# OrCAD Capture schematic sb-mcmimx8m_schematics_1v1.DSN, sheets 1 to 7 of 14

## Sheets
1 13. CAN interfaces: size A4; title: SBC-MCM-iMX8M    13. CAN interfaces; rev: 1.0; note: 8000136001; note: 17 HaYetsira Street; note: Yokneam Illit, Israel 2069208
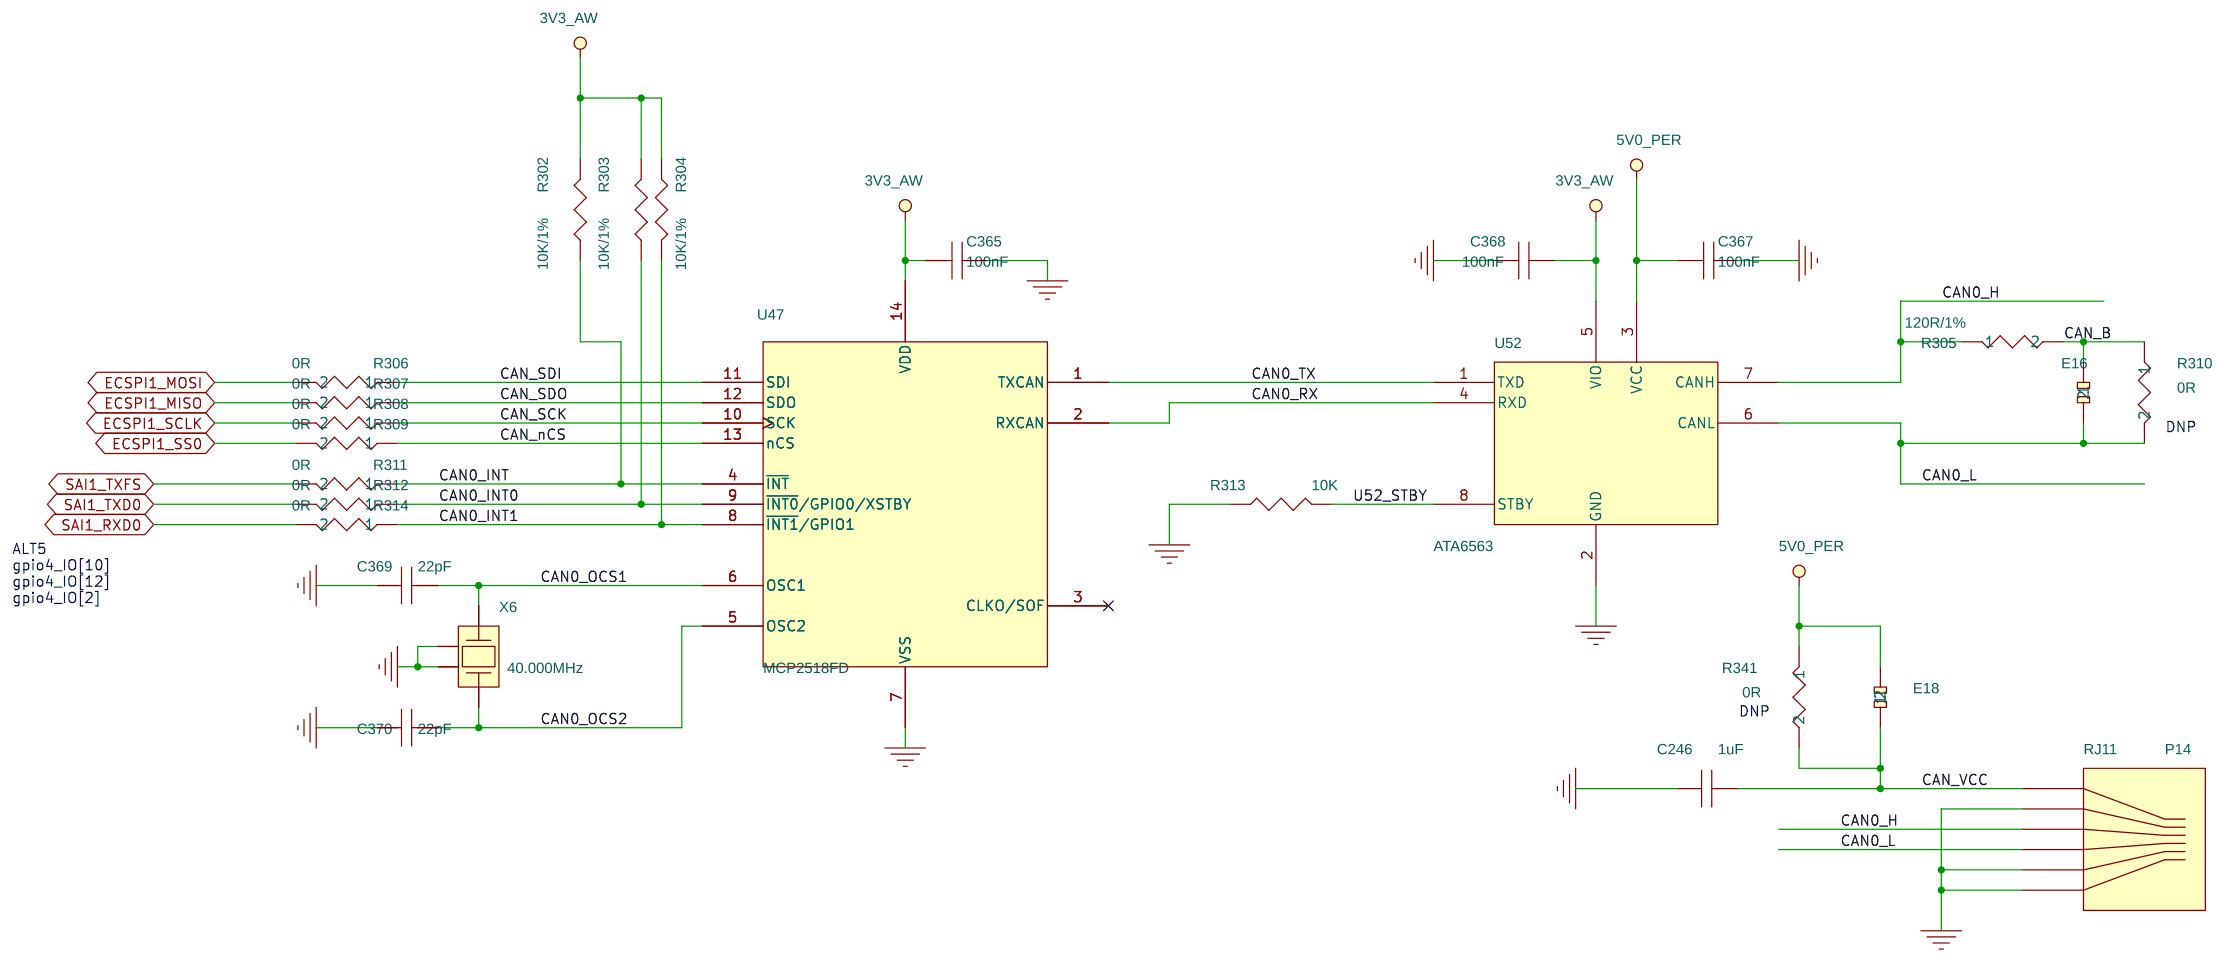
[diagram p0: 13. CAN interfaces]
2 01. Block Diagram: size C; title: SBC-MCM-iMX8M    01. INDEX; rev: 2.0
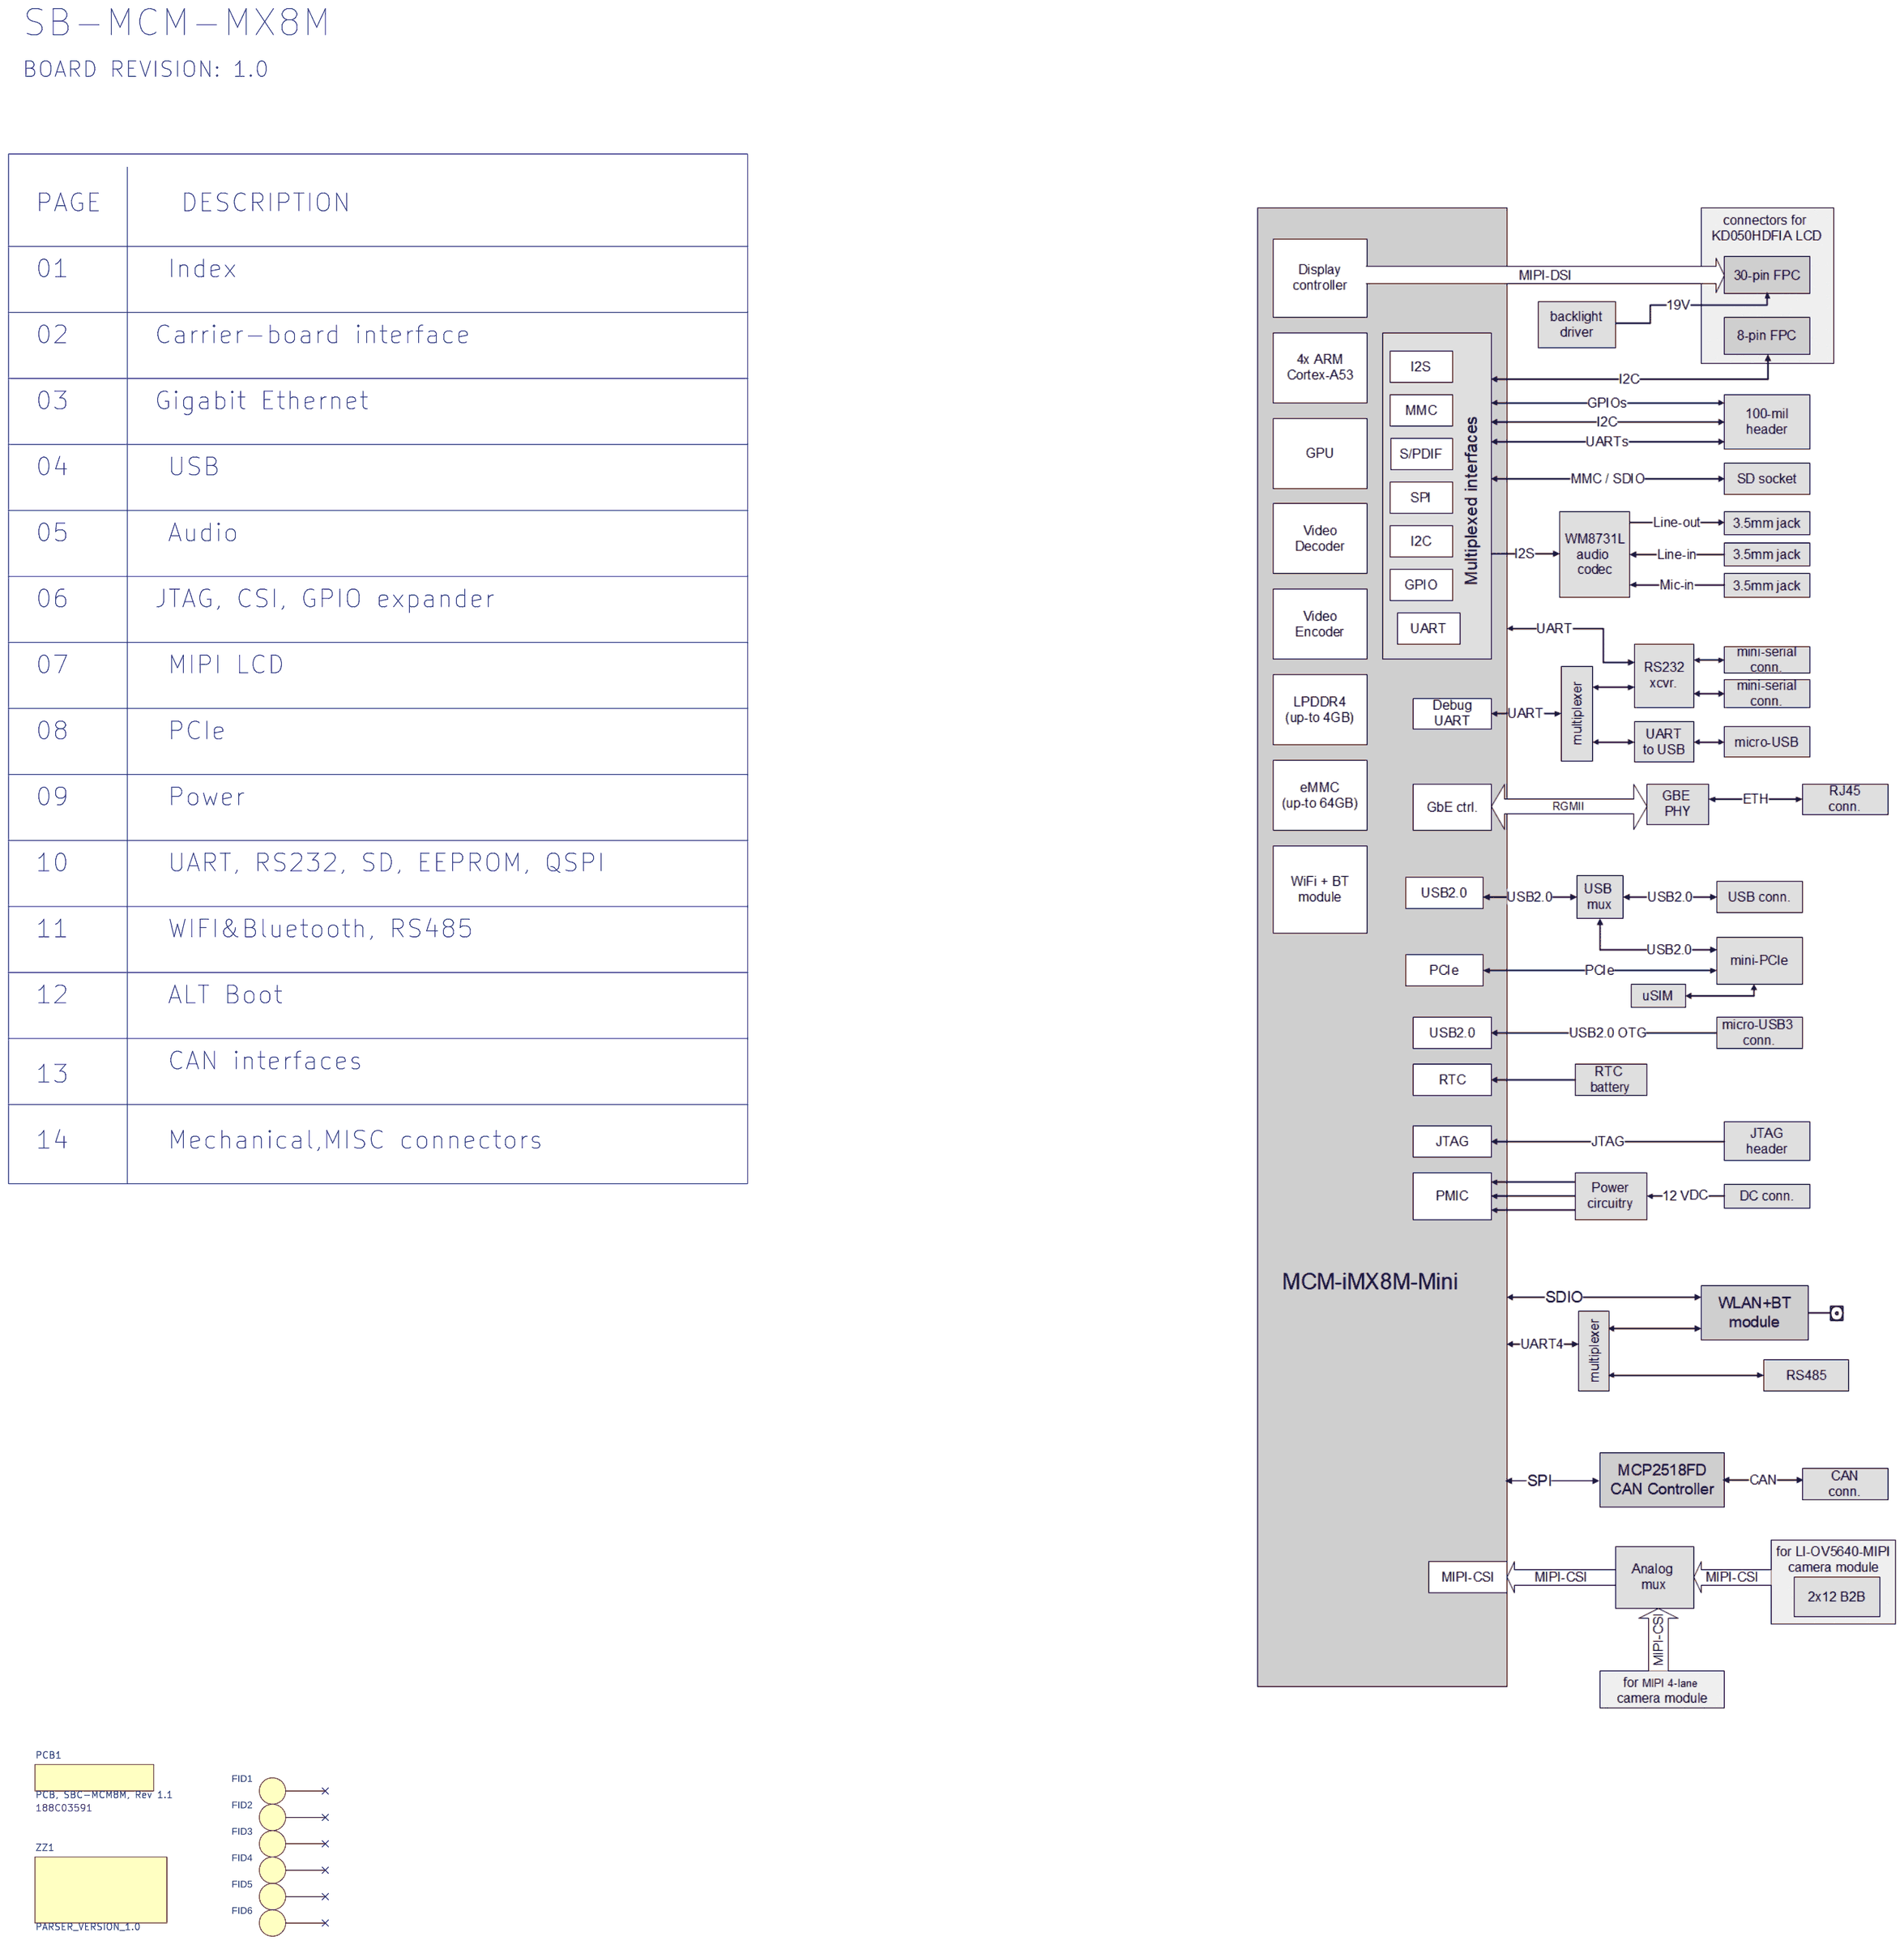
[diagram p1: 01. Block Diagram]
3 02. Carrier Board interface: size A3; title: SBC-MCM-iMX8M    02.140 QFN package
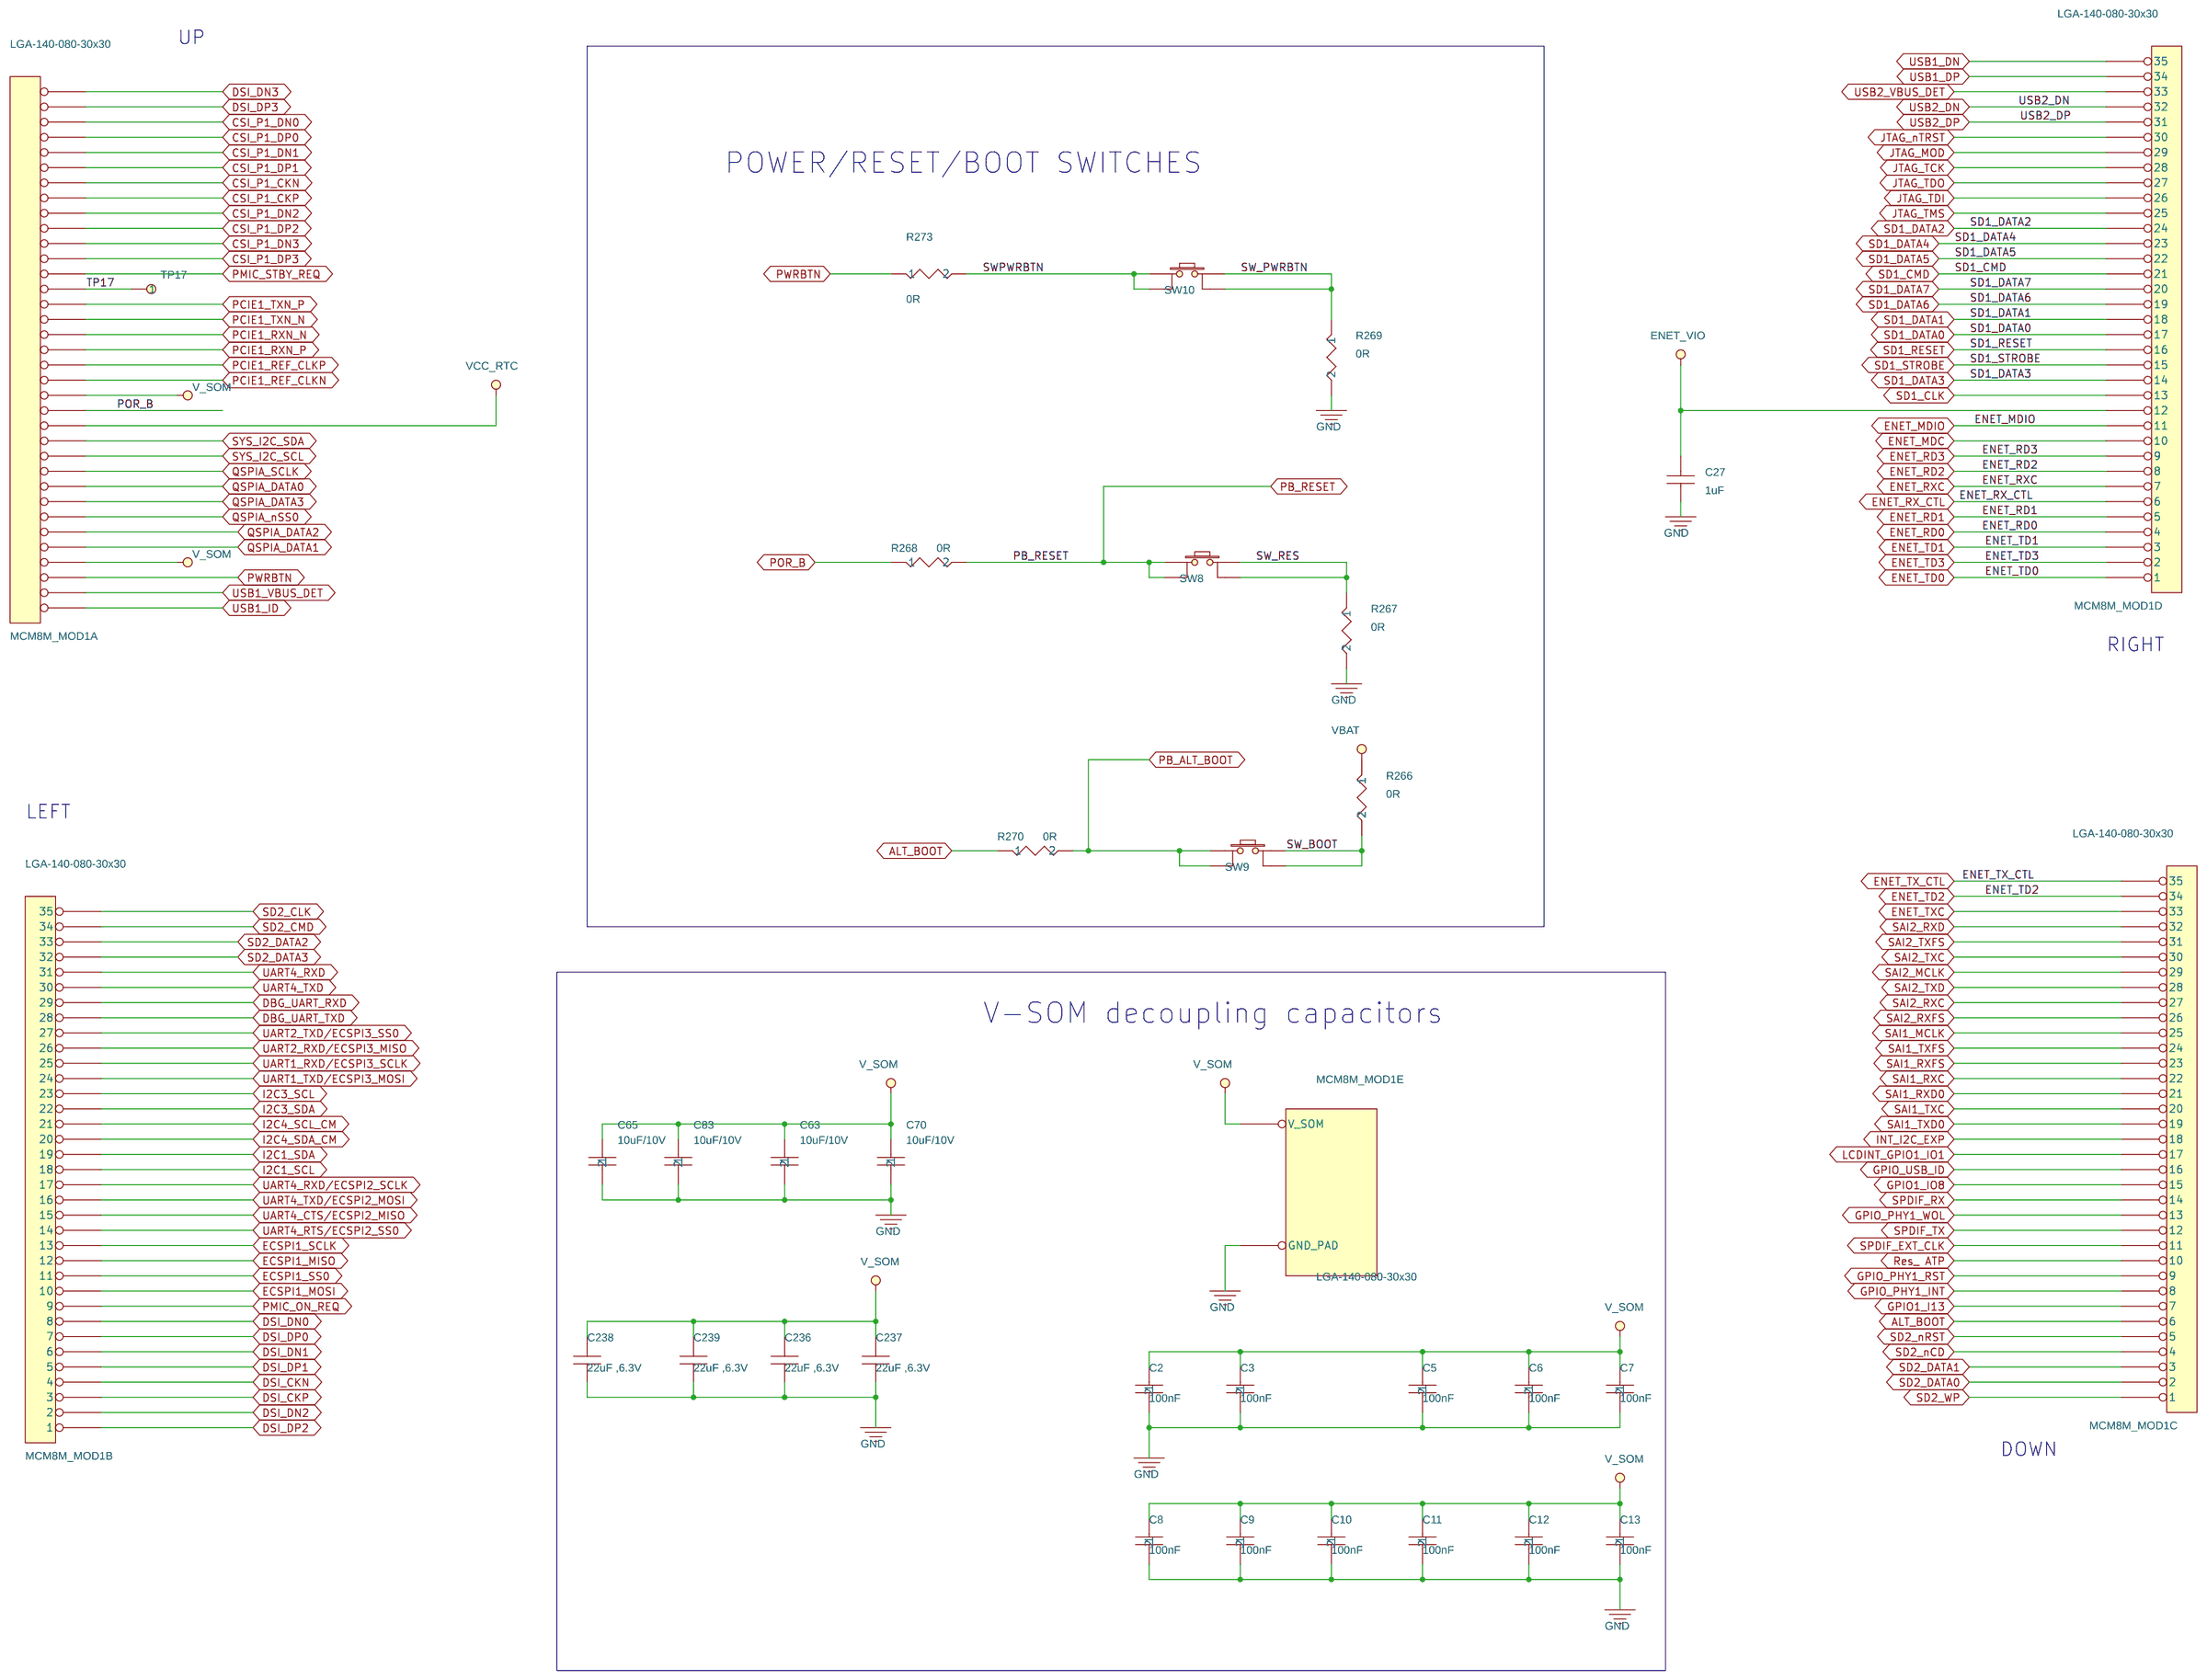
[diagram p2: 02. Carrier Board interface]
4 03. Gigabit Ethernet: size A2; title: SBC-MCM-iMX8M      03. Gigabit Ethernet; rev: 2.0
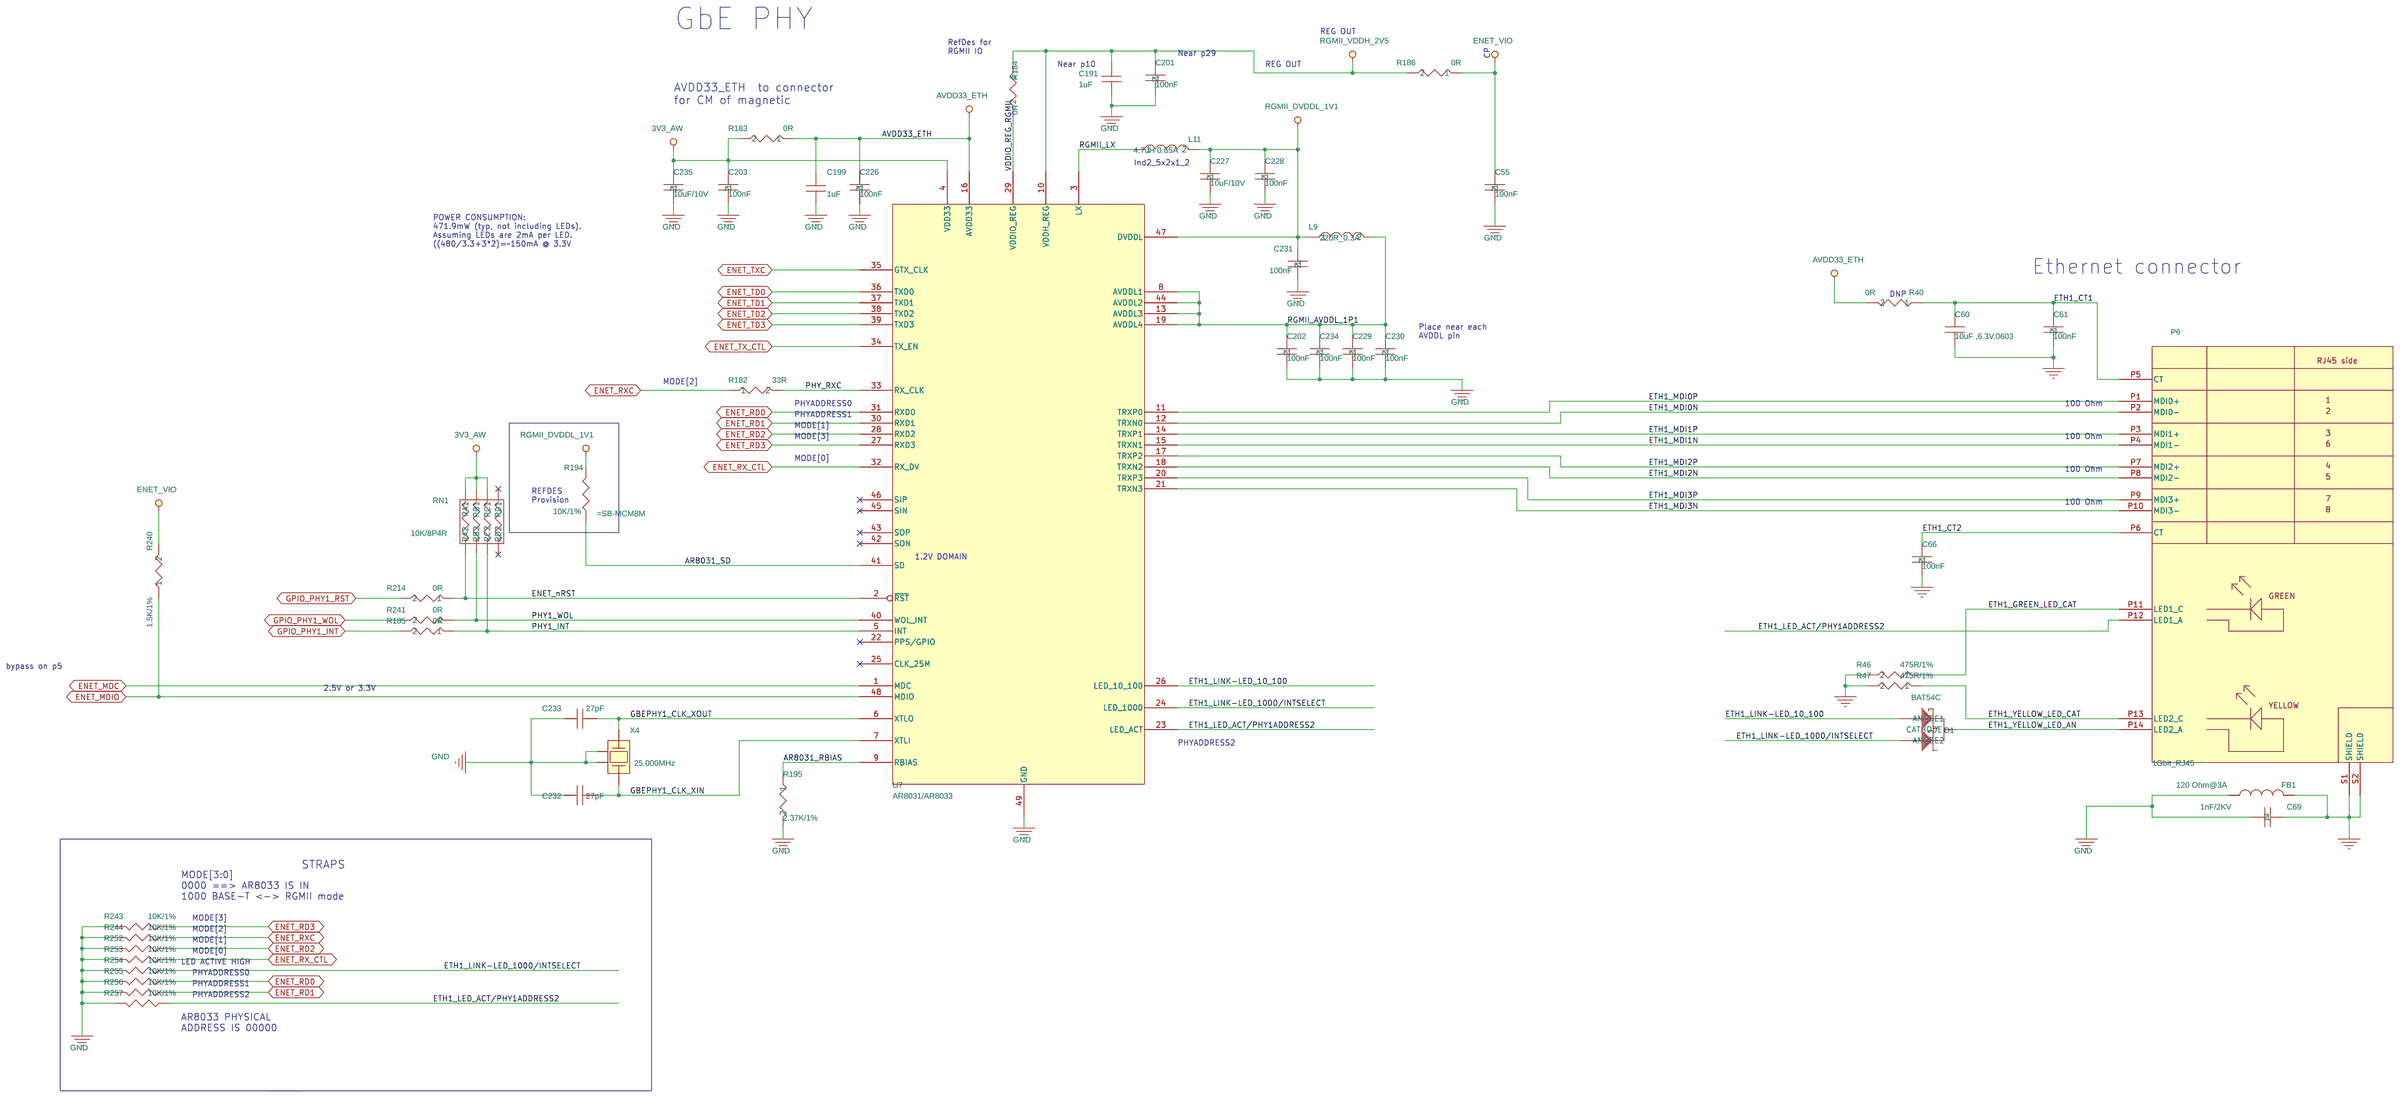
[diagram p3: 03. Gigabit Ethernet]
5 04. USB: size A3; title: SBC-MCM-iMX8M    04. USB; rev: 2.0
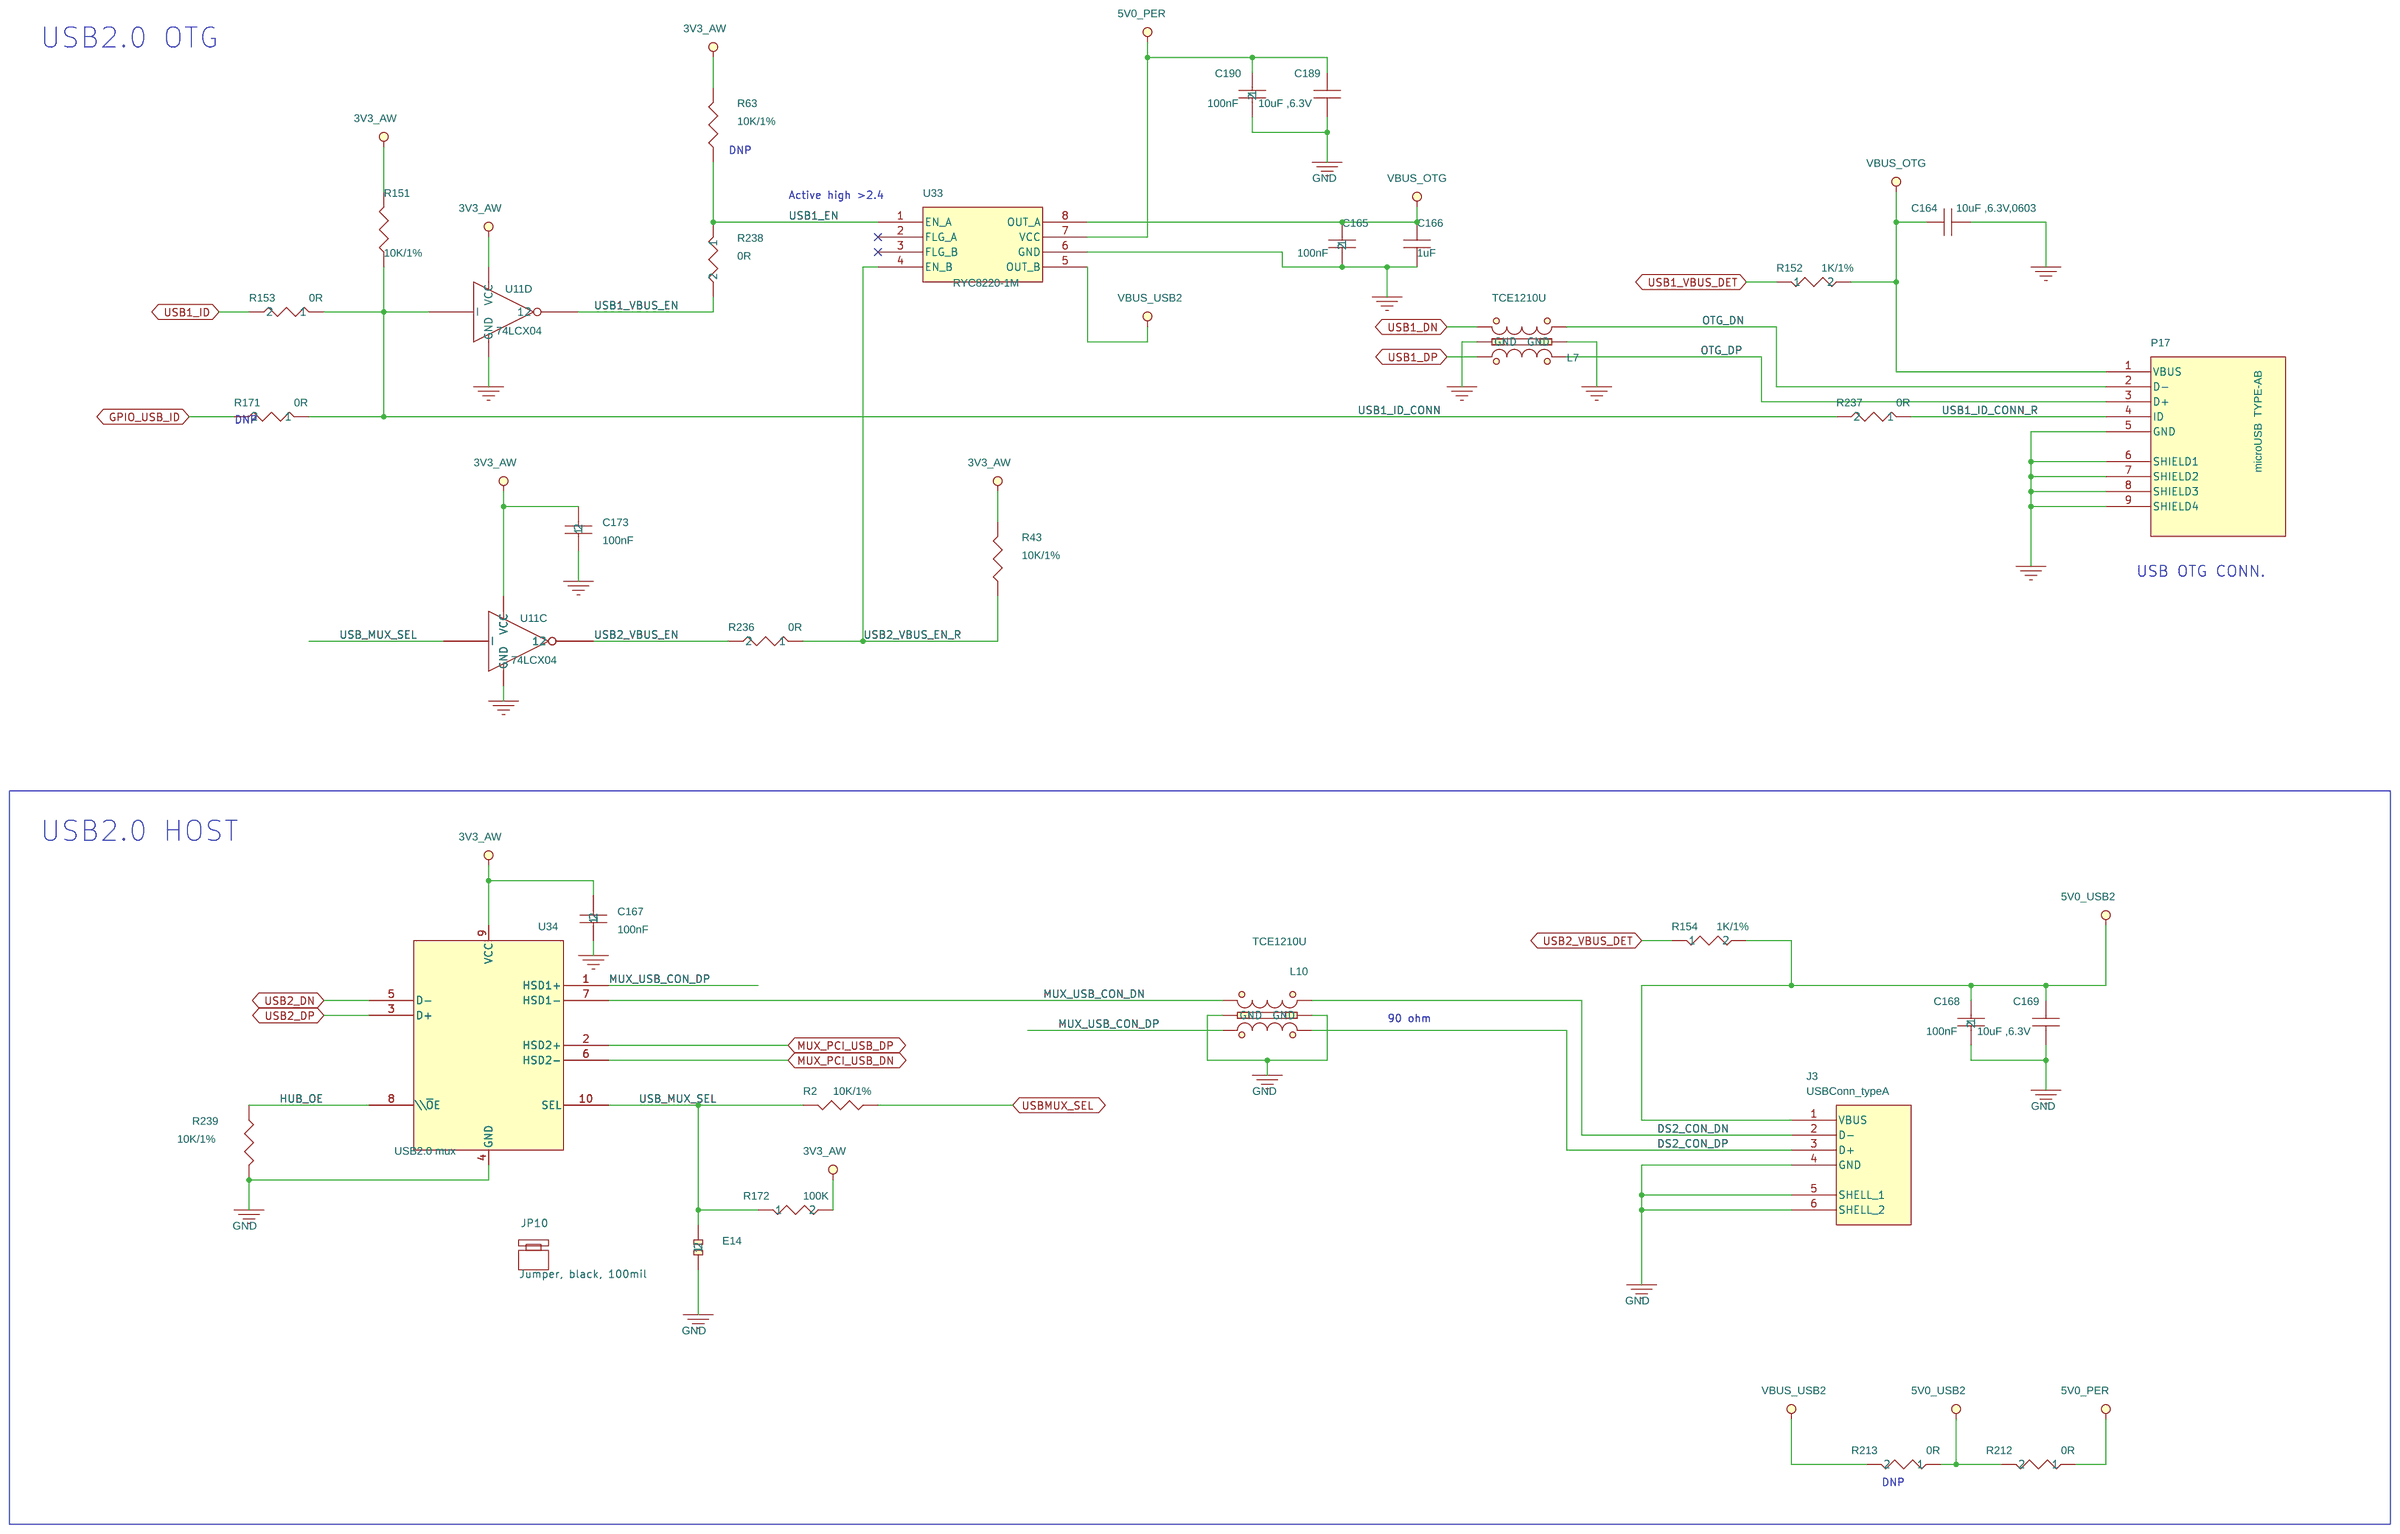
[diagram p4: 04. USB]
6 05. Audio: size B; title: SBC-MCM-iMX8M      05. AUDIO,SPDIF; rev: 2.0
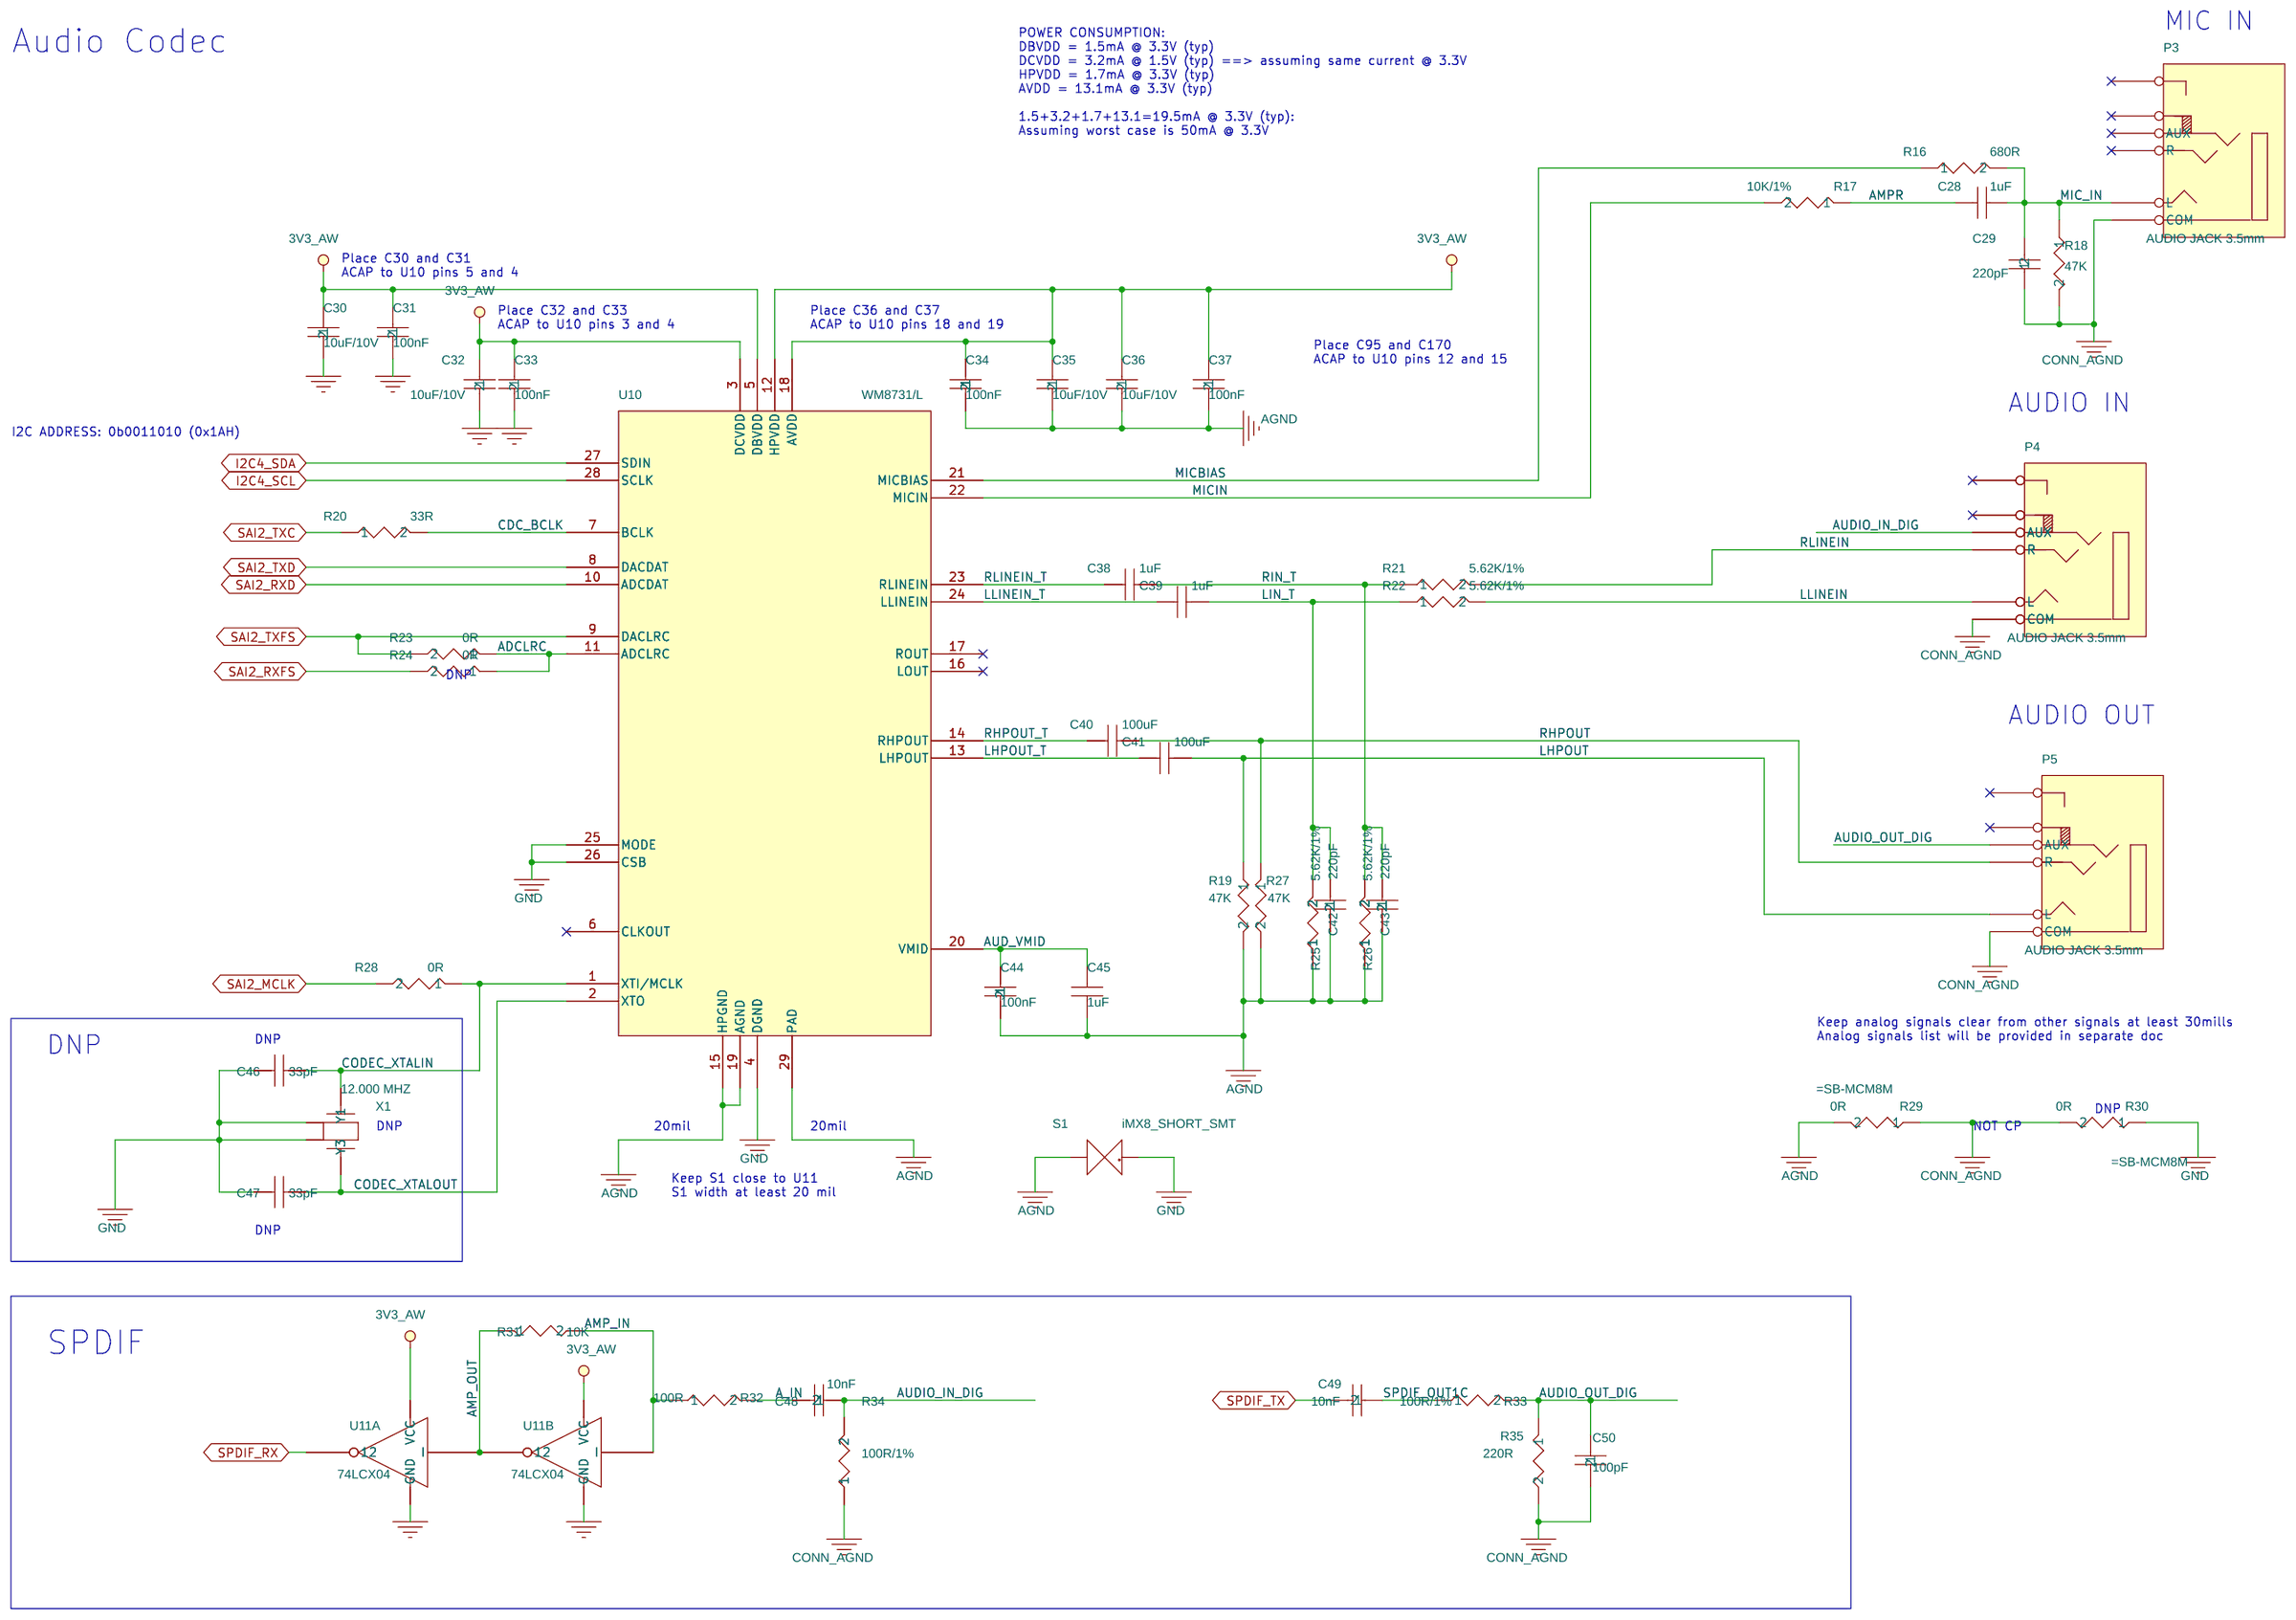
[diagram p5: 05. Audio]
7 06. JTAG, CSI, GPIO expander: size A2; title: SBC-MCM-iMX8M    06. JTAG,CSI,MISK; rev: 2.0
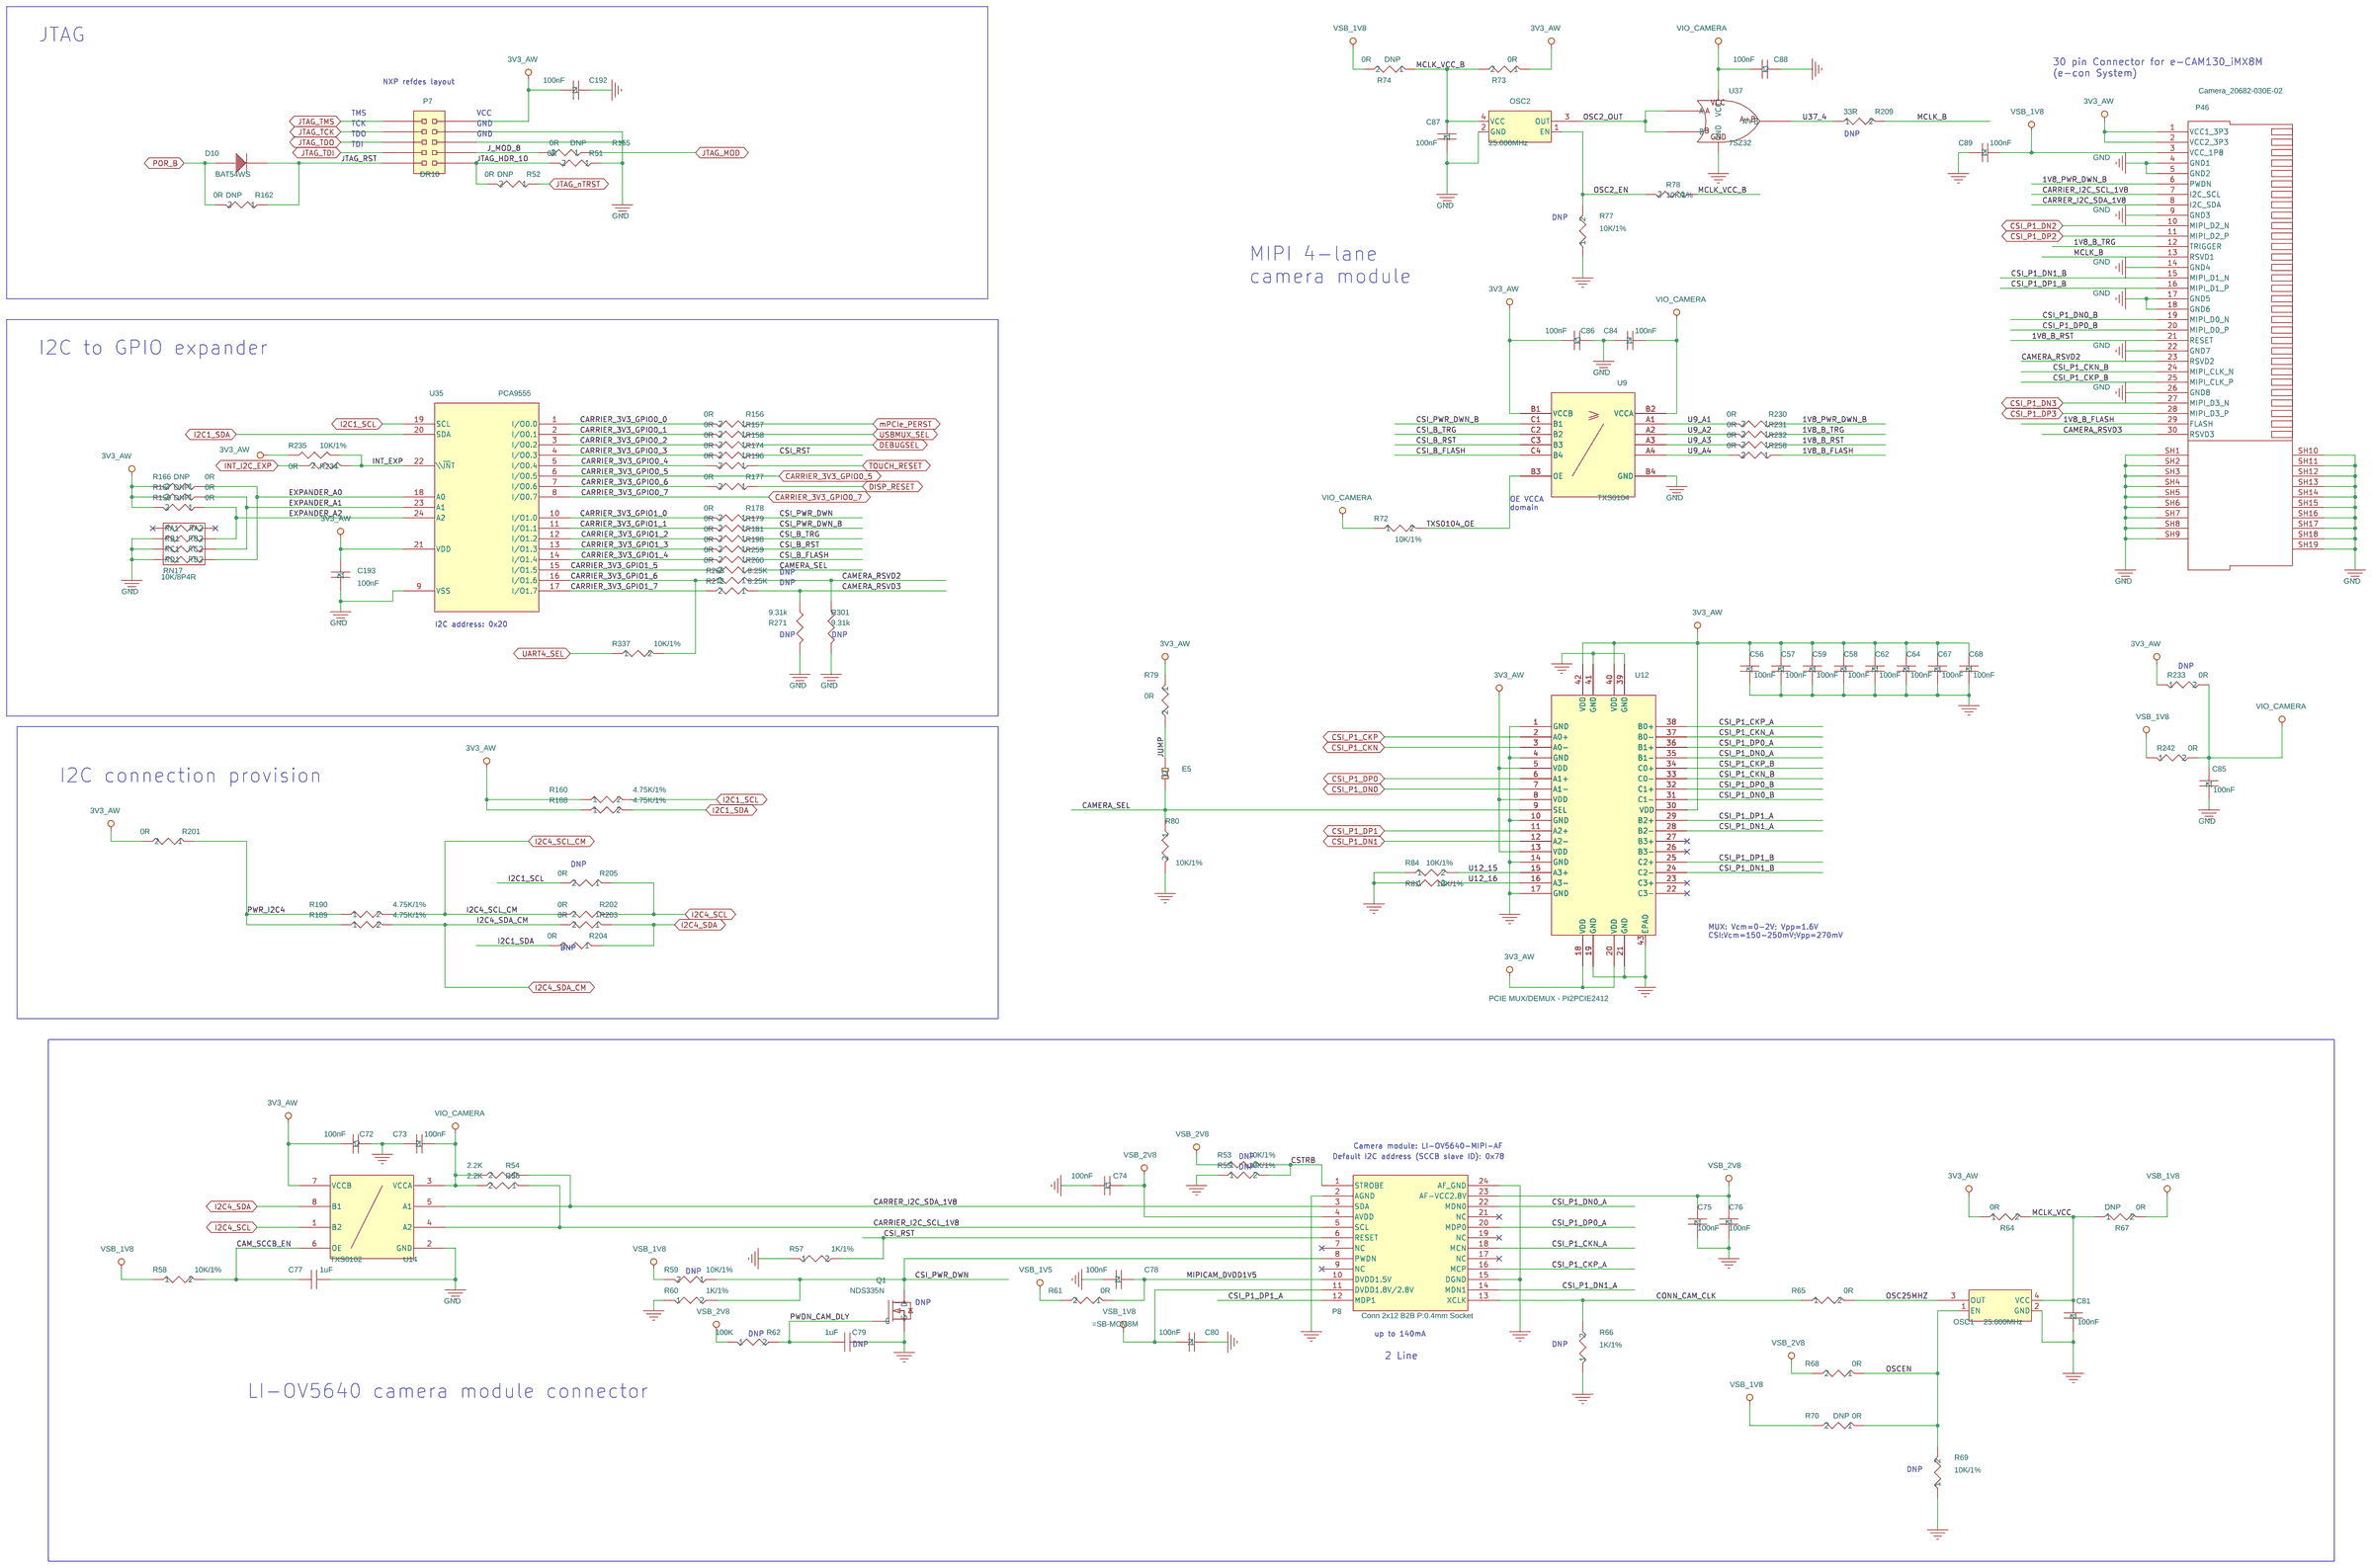
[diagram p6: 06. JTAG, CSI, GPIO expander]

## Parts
sheet 01. Block Diagram
FID1  FIDUCIAL  [FIDUCIAL]
FID2  FIDUCIAL  [FIDUCIAL]
FID3  FIDUCIAL  [FIDUCIAL]
FID4  FIDUCIAL  [FIDUCIAL]
FID5  FIDUCIAL  [FIDUCIAL]
FID6  FIDUCIAL  [FIDUCIAL]
PCB1  PCB, SBC-MCM8M, Rev 1.1
ZZ1  PARSER_VERSION_1.0
sheet 02. Carrier Board interface
C2  100nF  [RC0402]
C3  100nF  [RC0402]
C5  100nF  [RC0402]
C6  100nF  [RC0402]
C7  100nF  [RC0402]
C8  100nF  [RC0402]
C9  100nF  [RC0402]
C10  100nF  [RC0402]
C11  100nF  [RC0402]
C12  100nF  [RC0402]
C13  100nF  [RC0402]
C27  1uF  [RC0402]
C63  10uF/10V  [0402]
C65  10uF/10V  [0402]
C70  10uF/10V  [0402]
C83  10uF/10V  [0402]
C236  22uF ,6.3V  [RC0603]
C237  22uF ,6.3V  [RC0603]
C238  22uF ,6.3V  [RC0603]
C239  22uF ,6.3V  [RC0603]
MCM8M_MOD1  LGA-140-080-30x30  [LGA-140-080-30x30]  (sections A,B,C,D,E)
R266  0R  [RC0402]
R267  0R  [RC0402]
R268  0R  [RC0402]
R269  0R  [RC0402]
R270  0R  [RC0402]
R273  0R  [RC0402]
SW8  PushB  [TACTSW6x6SM]
SW9  PushB  [TACTSW6x6SM]
SW10  PushB  [TACTSW6x6SM]
TP17  TESTPOINT  [TESTPOINT]
sheet 03. Gigabit Ethernet
C55  100nF  [RC0402]
C60  10uF ,6.3V,0603  [RC0603]
C61  100nF  [RC0402]
C66  100nF  [RC0402]
C69  1nF/2KV  [C1812]
C191  1uF  [RC0402]
C199  1uF  [RC0402]
C201  100nF  [RC0402]
C202  100nF  [RC0402]
C203  100nF  [RC0402]
C226  100nF  [RC0402]
C227  10uF/10V  [0402]
C228  100nF  [RC0402]
C229  100nF  [RC0402]
C230  100nF  [RC0402]
C231  100nF  [RC0402]
C232  27pF  [RC0402]
C233  27pF  [RC0402]
C234  100nF  [RC0402]
C235  10uF/10V  [0402]
D1  BAT54C  [SOT23]
FB1  120 Ohm@3A  [1206]
L9  220R_0.3A  [FB0402]
L11  4.7uH 0.65A  [Ind2_5x2x1_2]
P6  1Gbit_RJ45  [DUSBRJ-1G]
R40  0R  [RC0402]
R46  475R/1%  [RC0402]
R47  475R/1%  [RC0402]
R182  33R  [RC0402]
R183  0R  [RC0402]
R184  0R  [RC0402]
R185  0R  [RC0402]
R186  0R  [RC0402]
R194  10K/1%  [RC0402]
R195  2.37K/1%  [RC0402]
R214  0R  [RC0402]
R240  1.5K/1%  [RC0402]
R241  0R  [RC0402]
R243  10K/1%  [RC0402]
R244  10K/1%  [RC0402]
R252  10K/1%  [RC0402]
R253  10K/1%  [RC0402]
R254  10K/1%  [RC0402]
R255  10K/1%  [RC0402]
R256  10K/1%  [RC0402]
R257  10K/1%  [RC0402]
RN1  10K/8P4R  [RESNET8P0805]
U7  AR8031/AR8033  [MO-220WJJE]
X4  25.000MHz  [OSC3225]
sheet 04. USB
C164  10uF ,6.3V,0603  [C0603-08]
C165  100nF  [RC0402]
C166  1uF  [RC0402]
C167  100nF  [RC0402]
C168  100nF  [RC0402]
C169  10uF ,6.3V  [C0603-08]
C173  100nF  [RC0402]
C189  10uF ,6.3V  [C0603-08]
C190  100nF  [RC0402]
E14  HDR1X2  [1X2THHDR]
J3  USBConn_typeA  [USB-A-SM]
JP10  Jumper, black, 100mil
L7  TCE1210U  [EMI1012-ESD]
L10  TCE1210U  [EMI1012-ESD]
P17  microUSB  TYPE-AB  [MICRO-USB-AB-RA-SM]
R2  10K/1%  [RC0402]
R43  10K/1%  [RC0402]
R63  10K/1%  [RC0402]
R151  10K/1%  [RC0402]
R152  1K/1%  [RC0402]
R153  0R  [RC0402]
R154  1K/1%  [RC0402]
R171  0R  [RC0402]
R172  100K  [RC0402]
R212  0R  [RC1206]
R213  0R  [RC1206]
R236  0R  [RC0402]
R237  0R  [RC0402]
R238  0R  [RC0402]
R239  10K/1%  [RC0402]
U33  RYC8220-1M  [SO-8-150]
U34  USB2.0 mux  [MO-255U1418E]
sheet 05. Audio
C28  1uF  [RC0402]
C29  220pF  [RC0603]
C30  10uF/10V  [0402]
C31  100nF  [RC0402]
C32  10uF/10V  [0402]
C33  100nF  [RC0402]
C34  100nF  [RC0402]
C35  10uF/10V  [0402]
C36  10uF/10V  [0402]
C37  100nF  [RC0402]
C38  1uF  [RC0402]
C39  1uF  [RC0402]
C40  100uF  [C1206]
C41  100uF  [C1206]
C42  220pF  [RC0603]
C43  220pF  [RC0603]
C44  100nF  [RC0402]
C45  1uF  [RC0402]
C46  33pF  [RC0402]
C47  33pF  [RC0402]
C48  10nF  [RC0402]
C49  10nF  [RC0402]
C50  100pF  [RC0402]
P3  AUDIO JACK 3.5mm  [AJ35-4P-SW-SM]
P4  AUDIO JACK 3.5mm  [AJ35-4P-SW-SM]
P5  AUDIO JACK 3.5mm  [AJ35-4P-SW-SM]
R16  680R  [RC0402]
R17  10K/1%  [RC0402]
R18  47K  [RC0402]
R19  47K  [RC0402]
R20  33R  [RC0402]
R21  5.62K/1%  [RC0402]
R22  5.62K/1%  [RC0402]
R23  0R  [RC0402]
R24  0R  [RC0402]
R25  5.62K/1%  [RC0402]
R26  5.62K/1%  [RC0402]
R27  47K  [RC0402]
R28  0R  [RC0402]
R29  0R  [RC0402]
R30  0R  [RC0402]
R31  10K  [RC0402]
R32  100R  [RC0402]
R33  100R/1%  [RC0402]
R34  100R/1%  [RC0402]
R35  220R  [RC0402]
S1  iMX8_SHORT_SMT  [iMX8_SHORT_SMT]
U10  WM8731/L  [MO-220VHHD-1]
X1  12.000 MHZ  [OSC3225]
sheet 06. JTAG, CSI, GPIO expander
C56  100nF  [RC0402]
C57  100nF  [RC0402]
C58  100nF  [RC0402]
C59  100nF  [RC0402]
C62  100nF  [RC0402]
C64  100nF  [RC0402]
C67  100nF  [RC0402]
C68  100nF  [RC0402]
C72  100nF  [RC0402]
C73  100nF  [RC0402]
C74  100nF  [RC0402]
C75  100nF  [RC0402]
C76  100nF  [RC0402]
C77  1uF  [RC0402]
C78  100nF  [RC0402]
C79  1uF  [RC0402]
C80  100nF  [RC0402]
C81  100nF  [RC0402]
C84  100nF  [RC0402]
C85  100nF  [RC0402]
C86  100nF  [RC0402]
C87  100nF  [RC0402]
C88  100nF  [RC0402]
C89  100nF  [RC0402]
C192  100nF  [RC0402]
C193  100nF  [RC0402]
D10  BAT54WS  [SOD-323]
E5  HDR1X2  [1X2THHDR]
OSC1  25.000MHz  [OSC3225]
OSC2  25.000MHz  [OSC3225]
P7  DR10  [2X5THHDR]
P8  Conn 2x12 B2B P:0.4mm Socket  [B2B04M2X12R]
P46  Camera_20682-030E-02  [CON30]
Q1  NDS335N  [SOT23]
R51  0R  [RC0402]
R52  0R  [RC0402]
R53  10K/1%  [RC0402]
R54  2.2K  [RC0402]
R55  10K/1%  [RC0402]
R56  2.2K  [RC0402]
R57  1K/1%  [RC0402]
R58  10K/1%  [RC0402]
R59  10K/1%  [RC0402]
R60  1K/1%  [RC0402]
R61  0R  [RC0402]
R62  100K  [RC0402]
R64  0R  [RC0402]
R65  0R  [RC0402]
R66  1K/1%  [RC0402]
R67  0R  [RC0402]
R68  0R  [RC0402]
R69  10K/1%  [RC0402]
R70  0R  [RC0402]
R72  10K/1%  [RC0402]
R73  0R  [RC0402]
R74  0R  [RC0402]
R77  10K/1%  [RC0402]
R78  10K/1%  [RC0402]
R79  0R  [RC0402]
R80  10K/1%  [RC0402]
R81  10K/1%  [RC0402]
R84  10K/1%  [RC0402]
R155  0R  [RC0402]
R156  0R  [RC0402]
R157  0R  [RC0402]
R158  0R  [RC0402]
R159  0R  [RC0402]
R160  4.75K/1%  [RC0402]
R162  0R  [RC0402]
R166  0R  [RC0402]
R167  0R  [RC0402]
R174  0R  [RC0402]
R177  0R  [RC0402]
R178  0R  [RC0402]
R179  0R  [RC0402]
R181  0R  [RC0402]
R188  4.75K/1%  [RC0402]
R189  4.75K/1%  [RC0402]
R190  4.75K/1%  [RC0402]
R196  0R  [RC0402]
R198  0R  [RC0402]
R201  0R  [RC0402]
R202  0R  [RC0402]
R203  0R  [RC0402]
R204  0R  [RC0402]
R205  0R  [RC0402]
R209  33R  [RC0402]
R230  0R  [RC0402]
R231  0R  [RC0402]
R232  0R  [RC0402]
R233  0R  [RC0402]
R234  0R  [RC0402]
R235  10K/1%  [RC0402]
R242  0R  [RC0402]
R258  0R  [RC0402]
R259  0R  [RC0402]
R260  0R  [RC0402]
R265  8.25K  [RC0402]
R271  9.31k  [RC0402]
R272  8.25K  [RC0402]
R301  9.31k  [RC0402]
R337  10K/1%  [RC0402]
RN17  10K/8P4R  [RESNET8P0805]
U9  TXS0104  [BGA-12-05-2_1X2_6]
U12  PCIE MUX/DEMUX - PI2PCIE2412  [MO-220VMFD-2x7.5]
U14  TXS0102  [MO-187DA-8]
U35  PCA9555  [QFN4x4-24]
U37  7SZ32  [SC70]
sheet 10. UART, RS232, SD, EPROM,QSPI
U11  74LCX04  [TSSOP-14]  (sections A,B,C,D,E,F)
sheet 13. CAN interfaces
C246  1uF  [RC0402]
C365  100nF  [RC0402]
C367  100nF  [RC0402]
C368  100nF  [RC0402]
C369  22pF  [RC0402]
C370  22pF  [RC0402]
E16  HDR1X2  [1X2THHDR]
E18  HDR1X2  [1X2THHDR]
P14  RJ11  [RJ11TH6-6]
R302  10K/1%  [RC0402]
R303  10K/1%  [RC0402]
R304  10K/1%  [RC0402]
R305  120R/1%  [RC0603]
R306  0R  [RC0402]
R307  0R  [RC0402]
R308  0R  [RC0402]
R309  0R  [RC0402]
R310  0R  [RC0402]
R311  0R  [RC0402]
R312  0R  [RC0402]
R313  10K  [RC0402]
R314  0R  [RC0402]
R341  0R  [RC0402]
U47  MCP2518FD  [MO-220WGGD-5]
U52  ATA6563
X6  40.000MHz  [XTAL5x3-4]

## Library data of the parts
FID1-FID6 = TESTPOINT_2: CLABCONF0: DNP
PCB1 = PCB,_EM-X270_Rev_1_0.1: CLABCONF0: =SB-MCM8M; P/N: 188C03591
ZZ1 = PARSER_VERSION_1_1.0: CLABCONF0: DNP
C2 C230 = 100nF,_10V,_X7R,_10%,_0402_4: CLABCONF0: =SB-MCM8M; P/N: 151B10400S
C3 C201 = 100nF,_10V,_X7R,_10%,_0402_6: CLABCONF0: =SB-MCM8M; P/N: 151B10400S
C5 C203 = 100nF,_10V,_X7R,_10%,_0402_7: CLABCONF0: =SB-MCM8M; P/N: 151B10400S
C6 C226 = 100nF,_10V,_X7R,_10%,_0402_8: CLABCONF0: =SB-MCM8M; P/N: 151B10400S
C7 C202 = 100nF,_10V,_X7R,_10%,_0402_9: CLABCONF0: =SB-MCM8M; P/N: 151B10400S
C8 C234 = 100nF,_10V,_X7R,_10%,_0402_10: CLABCONF0: =SB-MCM8M; P/N: 151B10400S
C9 = 100nF,_10V,_X7R,_10%,_0402: CLABCONF0: =SB-MCM8M; P/N: 151B10400S
C10 C228 = 100nF,_10V,_X7R,_10%,_0402_1: CLABCONF0: =SB-MCM8M; P/N: 151B10400S
C11 C229 = 100nF,_10V,_X7R,_10%,_0402_2: CLABCONF0: =SB-MCM8M; P/N: 151B10400S
C12 = 100nF,_10V,_X7R,_10%,_0402_3: CLABCONF0: =SB-MCM8M; P/N: 151B10400S
C13 C231 = 100nF,_10V,_X7R,_10%,_0402_5: CLABCONF0: =SB-MCM8M; P/N: 151B10400S
C27 C28 C38 C39 C45 C77 C166 C246 = 1uF,X5R,6.3V,0402: CLABCONF0: =SB-MCM8M
C32 C63 C227 = 10uF_10V_20%_0402_1: CLABCONF0: =SB-MCM8M
C35 C65 = 10uF_10V_20%_0402_2: CLABCONF0: =SB-MCM8M
C36 C70 = 10uF_10V_20%_0402_3: CLABCONF0: =SB-MCM8M
C30 C83 C235 = 10uF_10V_20%_0402: CLABCONF0: =SB-MCM8M
C236 = 22uF,6.3V,X5R: CLABCONF0: =SB-MCM8M; P/N: 151B22610S
C237 = 22uF,6.3V,X5R_1: CLABCONF0: =SB-MCM8M; P/N: 151B22610S
C238 = 22uF,6.3V,X5R_2: CLABCONF0: =SB-MCM8M; P/N: 151B22610S
C239 = 22uF,6.3V,X5R_3: CLABCONF0: =SB-MCM8M; P/N: 151B22610S
MCM8M_MOD1 = PAD_140: CLABCONF0: 503M013131=CQMD2N16; CLABCONF1: 503M013141=CDMD2N32; CLABCONF2: 503M012870=C0; P/N: 503M013131
R202 R266 = 0R,_0402_0: CLABCONF0: =SB-MCM8M; P/N: 161C00005S
R201 R267 = 0R,_0402_0_1: CLABCONF0: =SB-MCM8M; P/N: 161C00005S
R242 R268 = 0R,_0402_0_2: CLABCONF0: =SB-MCM8M; P/N: 161C00005S
R79 R269 = 0R,_0402_0_4: CLABCONF0: =SB-MCM8M; P/N: 161C00005S
R234 R270 = 0R,_0402_0_5: CLABCONF0: =SB-MCM8M; P/N: 161C00005S
R273 = 0R,_0402_0_3: CLABCONF0: =SB-MCM8M; P/N: 161C00005S
SW8-SW10 = TACT_SW_6x6mm_SMT: CLABCONF0: =SB-MCM8M
TP17 = TESTPOINT: CLABCONF0: DNP
C55 = 100nF,_10V,_X7R,_10%,_0402_11: CLABCONF0: =SB-MCM8M; P/N: 151B10400S
C60 = Cap.,10uF,6.3V,0603,X5R: CLABCONF0: =SB-MCM8M
C61 = 100nF,_10V,_X7R,_10%,_0402_3: CLABCONF0: =SB-MCM8M; Group: LAN2
C66 C167 = 100nF,_10V,_X7R,_10%,_0402: CLABCONF0: =SB-MCM8M; Group: LAN2
C69 = 1nF,_2KV,SMD_1812,_X7R,_10%: CLABCONF0: =SB-MCM8M
C191 C199 = 1uF,16V,0402: CLABCONF0: =SB-MCM8M
C232 C233 = 27pF,_50V,_X7R,_10%,_0402: CLABCONF0: =SB-MCM8M; P/N: 151D27000S
D1 = BAT54C: CLABCONF0: =SB-MCM8M
FB1 = Ferrite_bead_,_120_Ohm@3A: CLABCONF0: =SB-MCM8M
L9 = Ferrit_330R@100Mhz,0.2A: CLABCONF0: =SB-MCM8M; P/N: 147D22100S
L11 = Ind,_4.7uH,_30%,_1.2A,_0.07_ohm: CLABCONF0: =SB-MCM8M; P/N: 147A4R704S
P6 = Con_0.,1GBit_RJ45,_short: CLABCONF0: =SB-MCM8M
R40 R74 R171 = 0R,_0402_1: CLABCONF0: DNP
R46 = 475R_1%,_0402: CLABCONF0: =SB-MCM8M
R47 = 475R_1%,_0402_1: CLABCONF0: =SB-MCM8M
R182 = 33R,5%,0402,1_16W: CLABCONF0: =SB-MCM8M
R183 = 0R,_0402_0: CLABCONF0: =SB-MCM8M
R28 R184 = 0R,_0402_0_1: CLABCONF0: =SB-MCM8M
R185 = 0R,_0402_0_3: CLABCONF0: =SB-MCM8M
R186 = 0R,_0402_0_4: CLABCONF0: =SB-MCM8M
R194 = 10K,1%,0402,1_16W_0_5: CLABCONF0: =SB-MCM8M
R195 = 2.37K_1%,_0402: CLABCONF0: =SB-MCM8M
R214 = 0R,_0402_0_5: CLABCONF0: =SB-MCM8M
R240 = 1.5K_1%,_0402: CLABCONF0: =SB-MCM8M
R23 R241 = 0R,_0402_0_2: CLABCONF0: =SB-MCM8M
R243 = 10K,1%,0402,1_16W_0_6: CLABCONF0: =SB-MCM8M; P/N: 161C10021S
R244 = 10K,1%,0402,1_16W_0_7: CLABCONF0: =SB-MCM8M; P/N: 161C10021S
R252 = 10K,1%,0402,1_16W_0_8: CLABCONF0: =SB-MCM8M; P/N: 161C10021S
R253 R302 = 10K,1%,0402,1_16W_0: CLABCONF0: =SB-MCM8M; P/N: 161C10021S
R254 = 10K,1%,0402,1_16W_0_1: CLABCONF0: =SB-MCM8M; P/N: 161C10021S
R255 R303 = 10K,1%,0402,1_16W_0_2: CLABCONF0: =SB-MCM8M; P/N: 161C10021S
R256 R304 = 10K,1%,0402,1_16W_0_3: CLABCONF0: =SB-MCM8M; P/N: 161C10021S
R257 = 10K,1%,0402,1_16W_0_4: CLABCONF0: =SB-MCM8M; P/N: 161C10021S
RN1 RN17 = RN,10K,8P4R@0805: CLABCONF0: =SB-MCM8M
U7 = AR8031_QFN48_0: IC XCVR ETHERNET PHY 10/100/1000G-BIT 3.3V QFN48; CLABCONF0: =SB-MCM8M; HEIGHT: 0.8MM; MFG_NAME01: Atheros Communications, Inc; MFG_PN01: AR8031-AL1A; P/N: 116A00050S; PRIORITY_PN: 051-AR8031; ROHS: Yes
X4 = XTAL,_25.000Mhz,_3x5mm: CLABCONF0: =SB-MCM8M; P/N: 141B25603I
C164 C169 C189 = 10uF,6_0.3V,0603,20%X5R: CLABCONF0: =SB-MCM8M
C37 C86 C165 = 100nF,_10V,_X7R,_10%,_0402_2: CLABCONF0: =SB-MCM8M
C44 C84 C168 = 100nF,_10V,_X7R,_10%,_0402_3: CLABCONF0: =SB-MCM8M
C173 = 100nF,_10V,_X7R,_10%,_0402_1: CLABCONF0: =SB-MCM8M; Group: LAN2
C31 C89 C190 = 100nF,_10V,_X7R,_10%,_0402_4: CLABCONF0: =SB-MCM8M
E5 E14 E16 = HDR_1x2_100MIL_TH_JUMPER: CLABCONF0: =SB-MCM8M
J3 = USB_Conn.,_Fem,_Type_A_,_TH,_RA: CLABCONF0: =SB-MCM8M
JP10 = Jumper,_black,_100mil: CLABCONF0: =SB-MCM8M
L7 L10 = ESD_CHOKE_DIFFx2_10: CLABCONF0: =SB-MCM8M; P/N: 142D11801S
P17 = Conn.,_Micro-USB,_B-Type: CLABCONF0: =SB-MCM8M; P/N: 180K00502S
R2 = 10K,1%,0402,1_16W_0_3: CLABCONF0: =SB-MCM8M
R43 = 10K,1%,0402,1_16W_0_1: CLABCONF0: =SB-MCM8M
R63 = 10K,1%,0402,1_16W_0_2: CLABCONF0: DNP
R151 R235 = 10K,1%,0402,1_16W_0: CLABCONF0: =SB-MCM8M
R60 R152 = 1K,1%,0402,1_16W_1: CLABCONF0: =SB-MCM8M; Group: CAN
R65 R153 R307 = 0R,_0402_1_2: CLABCONF0: =SB-MCM8M
R57 R154 = 1K,1%,0402,1_16W: CLABCONF0: =SB-MCM8M; Group: CAN
R62 R172 = 100K,_0402: CLABCONF0: =SB-MCM8M; P/N: 161C10031S
R212 = 0R,_1206: CLABCONF0: =SB-MCM8M
R213 = 0R,_1206_1: CLABCONF0: DNP
R30 R236 R311 = 0R,_0402_1_1: CLABCONF0: =SB-MCM8M
R178 R237 = 0R,_0402_1_4: CLABCONF0: =SB-MCM8M
R238 R314 = 0R,_0402_1_3: CLABCONF0: =SB-MCM8M
R239 = 10K,1%,0402,1_16W_0_4: CLABCONF0: =SB-MCM8M
U33 = RYC8220-1M_DUAL_USB_PWR_SWITCH: CLABCONF0: =SB-MCM8M
U34 = USB2_0.0_mux: CLABCONF0: =SB-MCM8M; P/N: 116A72220S
C29 = 220pF,50V,NPO,0603_2: CLABCONF0: =SB-MCM8M
C33 C81 = 100nF,_10V,_X7R,_10%,_0402: CLABCONF0: =SB-MCM8M
C34 C76 = 100nF,_10V,_X7R,_10%,_0402_1: CLABCONF0: =SB-MCM8M
C40 C41 = 100uF,_6.3V,_X5R,_20%,_1210: CLABCONF0: =SB-MCM8M; P/N: 151B10730S
C42 = 220pF,50V,NPO,0603_1: CLABCONF0: =SB-MCM8M
C43 = 220pF,50V,NPO,0603: CLABCONF0: =SB-MCM8M
C46 C47 = 33pF,50V,NPO,10%,0402_0: CLABCONF0: DNP
C48 = 10nF,_25V,_X7R,_10%,_0402_1: CLABCONF0: =SB-MCM8M
C49 = 10nF,_25V,_X7R,_10%,_0402: CLABCONF0: =SB-MCM8M
C50 = 100pF,_50V,_NPO,_5%,_0402: CLABCONF0: =SB-MCM8M
P3-P5 = Audio_JACK,_STEREO+AUX+SW_3.5mm: CLABCONF0: =SB-MCM8M
R16 = 47K,_0402_1: CLABCONF0: =SB-MCM8M; P/N: 161C68001S
R17 = 10K,1%,0402,1_16W_1: CLABCONF0: =SB-MCM8M
R18 = 47K,_0402: CLABCONF0: =SB-MCM8M
R19 = 47K,_0402_2: CLABCONF0: =SB-MCM8M
R20 = 33R,5%,0402,1_16W_0: CLABCONF0: =SB-MCM8M
R21 = 5.62K_1%,0402_3: CLABCONF0: =SB-MCM8M
R22 = 5.62K_1%,0402_1: CLABCONF0: =SB-MCM8M
R24 = 0R,_0402_0: CLABCONF0: DNP
R25 = 5.62K_1%,0402: CLABCONF0: =SB-MCM8M
R26 = 5.62K_1%,0402_2: CLABCONF0: =SB-MCM8M
R27 = 47K,_0402_3: CLABCONF0: =SB-MCM8M
R29 R309 = 0R,_0402_1: CLABCONF0: =SB-MCM8M
R31 R80 = 10K,1%,0402,1_16W: CLABCONF0: =SB-MCM8M
R32 = 100R,1%,0402,1_16W_1: CLABCONF0: =SB-MCM8M
R33 = 100R,1%,0402,1_16W_2: CLABCONF0: =SB-MCM8M
R34 = 100R,1%,0402,1_16W: CLABCONF0: =SB-MCM8M
R35 = 220R,5%,0402,1_16W: CLABCONF0: =SB-MCM8M
S1 = MISC_SHORT_NL: CLABCONF0: DNP; P/N: iMX8_SHORT
U10 = TSC2046_2: CLABCONF0: =SB-MCM8M; P/N: 117A10010S
X1 = TMP_0: CLABCONF0: DNP; P/N: 141B12604I
C56 = 100nF,_10V,_X7R,_10%,_0402_21: CLABCONF0: =SB-MCM8M
C57 = 100nF,_10V,_X7R,_10%,_0402_23: CLABCONF0: =SB-MCM8M
C58 = 100nF,_10V,_X7R,_10%,_0402_16: CLABCONF0: =SB-MCM8M
C59 = 100nF,_10V,_X7R,_10%,_0402_6: CLABCONF0: =SB-MCM8M
C62 = 100nF,_10V,_X7R,_10%,_0402_14: CLABCONF0: =SB-MCM8M
C64 = 100nF,_10V,_X7R,_10%,_0402_7: CLABCONF0: =SB-MCM8M
C67 = 100nF,_10V,_X7R,_10%,_0402_15: CLABCONF0: =SB-MCM8M
C68 = 100nF,_10V,_X7R,_10%,_0402_17: CLABCONF0: =SB-MCM8M
C72 = 100nF,_10V,_X7R,_10%,_0402_11: CLABCONF0: =SB-MCM8M
C73 = 100nF,_10V,_X7R,_10%,_0402_19: CLABCONF0: =SB-MCM8M
C74 = 100nF,_10V,_X7R,_10%,_0402_5: CLABCONF0: =SB-MCM8M
C75 = 100nF,_10V,_X7R,_10%,_0402_12: CLABCONF0: =SB-MCM8M
C78 = 100nF,_10V,_X7R,_10%,_0402_9: CLABCONF0: =SB-MCM8M
C79 = 1uF,X5R,6.3V,0402: CLABCONF0: DNP
C80 = 100nF,_10V,_X7R,_10%,_0402_10: CLABCONF0: =SB-MCM8M
C85 = 100nF,_10V,_X7R,_10%,_0402_20: CLABCONF0: =SB-MCM8M
C87 = 100nF,_10V,_X7R,_10%,_0402_22: CLABCONF0: =SB-MCM8M
C88 = 100nF,_10V,_X7R,_10%,_0402_18: CLABCONF0: =SB-MCM8M
C192 = 100nF,_10V,_X7R,_10%,_0402_8: CLABCONF0: =SB-MCM8M
C193 = 100nF,_10V,_X7R,_10%,_0402_13: CLABCONF0: =SB-MCM8M
D10 = BAT54WS_0: CLABCONF0: =SB-MCM8M
OSC1 OSC2 = Osc.,_50Mhz,50PPM,_3.3V: CLABCONF0: =SB-MCM8M; P/N: 141C25601S
P7 = HDR_2x5_100MIL_TH: CLABCONF0: =SB-MCM8M; Group: COM2
P8 = Conn_2x12_B2B_P_0.4mm_Socket: CLABCONF0: =SB-MCM8M; P/N: 182K02401S
P46 = Camera_20682-030E-02: CLABCONF0: =SB-MCM8M; P/N: 182K03002S
Q1 = N-MOSFET,NDS335N,100mOhm@2.5V: CLABCONF0: =SB-MCM8M
R51 = 0R,_0402_1_19: CLABCONF0: =SB-MCM8M
R52 = 0R,_0402_1_24: CLABCONF0: DNP
R53 = 10K,1%,0402,1_16W_1: CLABCONF0: DNP
R54 = 2.2K,5%,0402.1_16W: CLABCONF0: =SB-MCM8M
R55 = 10K,1%,0402,1_16W_7: CLABCONF0: DNP
R56 = 2.2K,5%,0402.1_16W_1: CLABCONF0: =SB-MCM8M
R58 = 10K,1%,0402,1_16W_8: CLABCONF0: =SB-MCM8M
R59 = 10K,1%,0402,1_16W_2: CLABCONF0: DNP
R61 R312 = 0R,_0402_1_8: CLABCONF0: =SB-MCM8M
R64 = 0R,_0402_1_10: CLABCONF0: =SB-MCM8M
R66 = 1K,1%,0402,1_16W_2: CLABCONF0: DNP; Group: CAN
R67 = 0R,_0402_1_1: CLABCONF0: DNP
R68 R308 = 0R,_0402_1_5: CLABCONF0: =SB-MCM8M
R69 = 10K,1%,0402,1_16W_11: CLABCONF0: DNP
R70 = 0R,_0402_1_27: CLABCONF0: DNP
R72 = 10K,1%,0402,1_16W_4: CLABCONF0: =SB-MCM8M
R73 = 0R,_0402_1_13: CLABCONF0: =SB-MCM8M
R77 = 10K,1%,0402,1_16W_9: CLABCONF0: DNP
R78 = 10K,1%,0402,1_16W_6: CLABCONF0: =SB-MCM8M
R81 = 10K,1%,0402,1_16W_5: CLABCONF0: =SB-MCM8M
R84 = 10K,1%,0402,1_16W_3: CLABCONF0: =SB-MCM8M
R155 = 0R,_0402_1_23: CLABCONF0: DNP
R156 = 0R,_0402_1_7: CLABCONF0: =SB-MCM8M
R157 = 0R,_0402_1_16: CLABCONF0: =SB-MCM8M
R158 = 0R,_0402_1_18: CLABCONF0: =SB-MCM8M
R159 = 0R,_0402_1_14: CLABCONF0: DNP
R160 = 4_0.75K,1%,0402,1_16W_3: CLABCONF0: =SB-MCM8M
R162 = 0R,_0402_1_9: CLABCONF0: DNP
R166 = 0R,_0402_1_3: CLABCONF0: DNP
R167 = 0R,_0402_1_20: CLABCONF0: DNP
R174 = 0R,_0402_1_21: CLABCONF0: =SB-MCM8M
R177 R306 = 0R,_0402_1_6: CLABCONF0: =SB-MCM8M
R179 = 0R,_0402_1_25: CLABCONF0: =SB-MCM8M
R181 = 0R,_0402_1_11: CLABCONF0: =SB-MCM8M
R188 = 4_0.75K,1%,0402,1_16W_1: CLABCONF0: =SB-MCM8M
R189 = 4_0.75K,1%,0402,1_16W_2: CLABCONF0: =SB-MCM8M
R190 = 4_0.75K,1%,0402,1_16W: CLABCONF0: =SB-MCM8M
R196 = 0R,_0402_1_28: CLABCONF0: =SB-MCM8M
R198 = 0R,_0402_1_15: CLABCONF0: =SB-MCM8M
R203 = 0R,_0402_0_7: CLABCONF0: =SB-MCM8M; P/N: 161C00005S
R204 = 0R,_0402_0_6: CLABCONF0: DNP; P/N: 161C00005S
R205 = 0R,_0402_0_3: CLABCONF0: DNP; P/N: 161C00005S
R209 = 33R,5%,0402,1_16W: CLABCONF0: DNP
R230 = 0R,_0402_1_12: CLABCONF0: =SB-MCM8M
R231 = 0R,_0402_1_17: CLABCONF0: =SB-MCM8M
R232 = 0R,_0402_1_30: CLABCONF0: =SB-MCM8M
R233 = 0R,_0402_0_8: CLABCONF0: DNP; P/N: 161C00005S
R258 = 0R,_0402_1_29: CLABCONF0: =SB-MCM8M
R259 = 0R,_0402_1_26: CLABCONF0: =SB-MCM8M
R260 = 0R,_0402_1_22: CLABCONF0: =SB-MCM8M
R265 = 1M_,5%,_0402_1: CLABCONF0: DNP; P/N: 161C82511S
R271 R301 = RESISTOR: CLABCONF0: DNP; P/N: 161C93111S
R272 = 1M_,5%,_0402: CLABCONF0: DNP; P/N: 161C82511S
R337 = 10K,1%,0402,1_16W_10: CLABCONF0: =SB-MCM8M
U9 = TXB0104_2: CLABCONF0: =SB-MCM8M; P/N: 116A01041S
U12 = PCIE_Mux_Demux_2_1: CLABCONF0: =SB-MCM8M; P/N: 116A24123S
U14 = TXS0102_0: CLABCONF0: =SB-MCM8M; P/N: 116A01020S
U35 = PCA9555: CLABCONF0: =SB-MCM8M
U37 = 7SZ32_OR_sgl_SC70: CLABCONF0: =SB-MCM8M
U11 = 74LCX04_sgl_gate_TSSOP-14: CLABCONF0: =SB-MCM8M
C365 C367 C368 = 100nF,_10V,_X7R,_10%,_0402_0: CLABCONF0: =SB-MCM8M
C369 C370 = 27pF,_50V,_X7R,_10%,_0402: CLABCONF0: =SB-MCM8M; P/N: 151D22000S
E18 = HDR_1x2_100MIL_TH_JUMPER_1: CLABCONF0: =SB-MCM8M
P14 = RJ11: CLABCONF0: =SB-MCM8M
R305 = 120R_1%,_0603: CLABCONF0: =SB-MCM8M
R310 = 0R,_0402_1_4: CLABCONF0: DNP
R313 = 10K,1%,0402,1_16W_0_1: CLABCONF0: =SB-MCM8M; Group: Always
R341 = 0R,_0402_1_7: CLABCONF0: DNP
U47 = MCP2515_0: CLABCONF0: =SB-MCM8M; P/N: 116B00520S
U52 = ATA6563: CLABCONF0: =SB-MCM8M; P/N: 116A00380S
X6 = XTAL,_25.000Mhz,_3x5mm: CLABCONF0: =SB-MCM8M; P/N: 141B40600S

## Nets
1V8_B_FLASH: P46.29(FLASH) R258.1
1V8_B_RST: P46.21(RESET) R232.1
1V8_B_TRG: P46.12(TRIGGER) R231.1
1V8_PWR_DWN_B: P46.6(PWDN) R230.1
3V3_AW: C30.1 C31.1 C32.1 C33.1 C34.1 C35.1 C36.1 C37.1 C56.1 C57.1 C58.1 C59.1 C62.1 C64.1 C67.1 C68.1 C72.1 C86.1 C167.2 C173.2 C192.2 C193.1 C203.1 C235.1 C365.2 C368.2 P7.1 P46.1(VCC1_3P3) P46.2(VCC2_3P3) R43.2 R63.2 R64.1 R73.1 R79.1 R151.2 R159.2 R160.1 R166.2 R167.2 R172.2 R183.2 R188.1 R201.2 R233.1 R235.1 R266.1 R302.1 R303.1 R304.1 RN1.1(RA1) RN1.2(RB1) RN1.3(RC1) U7.4(VDD33) U9.B1(VCCB) U10.3(DCVDD) U10.5(DBVDD) U10.12(HPVDD) U10.18(AVDD) U11.14(VCC) U12.5(VDD) U12.8(VDD) U12.13(VDD) U12.18(VDD) U12.20(VDD) U12.30(VDD) U12.40(VDD) U12.42(VDD) U14.7(VCCB) U34.9(VCC) U35.21(VDD) U47.14(VDD) U52.5(VIO) ; also on sheet 8 9 10 11 12 13 14
5V0_PER: C189.1 C190.1 C367.2 E18.2 R212.1 R341.1 U33.7(VCC) U52.3(VCC) ; also on sheet 10 14
5V0_USB2: C168.1 C169.1 J3.1(VBUS) R154.2 R212.2 R213.1
AGND: C34.2 C35.2 C36.2 C37.2 C42.2 C43.2 C44.2 C45.2 R19.2 R25.1 R26.1 R27.2 R29.2 S1.2 U10.15(HPGND) U10.19(AGND) U10.29(PAD) ; also on sheet 14
AVDD33_ETH: C199.2 C226.1 R40.2 R183.1 U7.16(AVDD33)
GND: C2.2 C3.2 C5.2 C6.2 C7.2 C8.2 C9.2 C10.2 C11.2 C12.2 C13.2 C27.1 C30.2 C31.2 C32.2 C33.2 C46.1 C47.1 C55.2 C56.2 C57.2 C58.2 C59.2 C60.2 C61.2 C62.2 C63.2 C64.2 C65.2 C66.2 C67.2 C68.2 C69.2 C70.2 C72.2 C73.2 C74.1 C75.2 C76.2 C77.2 C78.2 C79.1 C80.1 C81.2 C83.2 C84.2 C85.2 C86.2 C87.2 C88.2 C89.2 C164.2 C165.2 C166.2 C167.1 C168.2 C169.2 C173.1 C189.2 C190.2 C191.1 C192.1 C193.2 C199.1 C201.2 C202.2 C203.2 C226.2 C227.2 C228.2 C229.2 C230.2 C231.2 C232.1 C233.1 C234.2 C235.2 C236.1 C237.1 C238.1 C239.1 C246.1 C365.1 C367.1 C368.1 C369.1 C370.1 E14.1 FB1.2 J3.4(GND) J3.5(SHELL_1) J3.6(SHELL_2) L7.5(GND) L7.6(GND) L10.5(GND) L10.6(GND) MCM8M_MOD1.142(GND_PAD) OSC1.2(GND) OSC2.2(GND) P7.3 P7.5 P8.2(AGND) P8.15(DGND) P8.24(AF_GND) P14.2 P14.5 P14.6 P17.5(GND) P17.6(SHIELD1) P17.7(SHIELD2) P17.8(SHIELD3) P17.9(SHIELD4) P46.4(GND1) P46.5(GND2) P46.9(GND3) P46.14(GND4) P46.17(GND5) P46.18(GND6) P46.22(GND7) P46.26(GND8) P46.SH1 P46.SH2 P46.SH3 P46.SH4 P46.SH5 P46.SH6 P46.SH7 P46.SH8 P46.SH9 P46.SH10 P46.SH11 P46.SH12 P46.SH13 P46.SH14 P46.SH15 P46.SH16 P46.SH17 P46.SH18 P46.SH19 Q1.2(S) R30.1 R46.2 R47.2 R51.1 R55.1 R57.1 R60.1 R66.1 R69.1 R77.1 R80.2 R81.1 R84.1 R195.2 R239.1 R243.2 R244.2 R252.2 R253.2 R254.2 R255.2 R256.2 R257.2 R267.2 R269.2 R271.2 R301.2 R313.1 RN17.2(RB1) RN17.3(RC1) RN17.4(RD1) S1.1 U7.49(GND) U9.B4(GND) U10.4(DGND) U10.25(MODE) U10.26(CSB) U11.7(GND) U12.1(GND) U12.4(GND) U12.10(GND) U12.14(GND) U12.17(GND) U12.19(GND) U12.21(GND) U12.39(GND) U12.41(GND) U12.43(EPAD) U14.2(GND) U33.6(GND) U34.4(GND) U35.9(VSS) U37.3(GND) U47.7(VSS) U52.2(GND) X1.2 X1.4 X4.2 X4.4 X6.2 X6.4 ; also on sheet 8 9 10 11 12 13 14
VBUS_OTG: C164.1 C165.1 C166.1 P17.1(VBUS) R152.2 U33.8(OUT_A)
VBUS_USB2: R213.2 U33.5(OUT_B)
VCC_RTC: MCM8M_MOD1.13 ; also on sheet 10
VDDIO_REG_RGMII: R184.2 U7.29(VDDIO_REG)
A_IN: C48.2 R32.2
ADCLRC: R23.1 R24.1 U10.11(ADCLRC)
ALT_BOOT: MCM8M_MOD1.76(6) R270.1 ; also on sheet 13
AMP_IN: R31.2 R32.1 U11.3(I)
AMP_OUT: R31.1 U11.1(I) U11.4(12)
AMPR: C28.2 R17.1
AR8031_RBIAS: R195.1 U7.9(RBIAS)
AR8031_SD: R194.1 U7.41(SD)
AUD_VMID: C44.1 C45.1 U10.20(VMID)
AUDIO_IN_DIG: C48.1 P4.2(AUX) R34.2
AUDIO_OUT_DIG: C50.1 P5.2(AUX) R33.2 R35.1
CAM_SCCB_EN: C77.1 R58.2 U14.6(OE)
CAMERA_RSVD2: P46.23(RSVD2) R265.1 R301.1
CAMERA_RSVD3: P46.30(RSVD3) R271.1 R272.1
CAMERA_SEL: E5.1 R80.1 R260.1 U12.9(SEL)
CAN0_H: P14.3 R305.1 U52.7(CANH)
CAN0_INT: R302.2 R311.1 U47.4(~{INT})
CAN0_INT0: R303.2 R312.1 U47.9(~{INT0}/GPIO0/XSTBY)
CAN0_INT1: R304.2 R314.1 U47.8(~{INT1}/GPIO1)
CAN0_L: E16.2 P14.4 R310.2 U52.6(CANL)
CAN0_OCS1: C369.2 U47.6(OSC1) X6.3
CAN0_OCS2: C370.2 U47.5(OSC2) X6.1
CAN0_RX: U47.2(RXCAN) U52.4(RXD)
CAN0_TX: U47.1(TXCAN) U52.1(TXD)
CAN_B: E16.1 R305.2 R310.1
CAN_nCS: R309.1 U47.13(nCS)
CAN_SCK: R308.1 U47.10(SCK)
CAN_SDI: R306.1 U47.11(SDI)
CAN_SDO: R307.1 U47.12(SDO)
CAN_VCC: C246.2 E18.1 P14.1 R341.2
CARRER_I2C_SDA_1V8: P8.3(SDA) P46.8(I2C_SDA) R54.1 U14.5(A1)
CARRIER_3V3_GPIO0_0: R156.2 U35.1(I/O0.0)
CARRIER_3V3_GPIO0_1: R157.2 U35.2(I/O0.1)
CARRIER_3V3_GPIO0_2: R158.2 U35.3(I/O0.2)
CARRIER_3V3_GPIO0_3: R174.2 U35.4(I/O0.3)
CARRIER_3V3_GPIO0_4: R196.2 U35.5(I/O0.4)
CARRIER_3V3_GPIO0_5: U35.6(I/O0.5) ; also on sheet 8
CARRIER_3V3_GPIO0_6: R177.2 U35.7(I/O0.6)
CARRIER_3V3_GPIO0_7: U35.8(I/O0.7) ; also on sheet 8
CARRIER_3V3_GPIO1_0: R178.2 U35.10(I/O1.0)
CARRIER_3V3_GPIO1_1: R179.2 U35.11(I/O1.1)
CARRIER_3V3_GPIO1_2: R181.2 U35.12(I/O1.2)
CARRIER_3V3_GPIO1_3: R198.2 U35.13(I/O1.3)
CARRIER_3V3_GPIO1_4: R259.2 U35.14(I/O1.4)
CARRIER_3V3_GPIO1_5: R260.2 U35.15(I/O1.5)
CARRIER_3V3_GPIO1_6: R265.2 R337.2 U35.16(I/O1.6)
CARRIER_3V3_GPIO1_7: R272.2 U35.17(I/O1.7)
CARRIER_I2C_SCL_1V8: P8.5(SCL) P46.7(I2C_SCL) R56.1 U14.4(A2)
CDC_BCLK: R20.2 U10.7(BCLK)
CODEC_XTALIN: C46.2 R28.1 U10.1(XTI/MCLK) X1.1(Y1)
CODEC_XTALOUT: C47.2 U10.2(XTO) X1.3(Y3)
CONN_AGND: C29.1 C50.2 P3.1(COM) P4.1(COM) P5.1(COM) R18.2 R29.1 R30.2 R34.1 R35.2
CONN_CAM_CLK: P8.13(XCLK) R65.1 R66.2
CSI_B_FLASH: R259.1 U9.C4(B4)
CSI_B_RST: R198.1 U9.C3(B3)
CSI_B_TRG: R181.1 U9.C2(B2)
CSI_P1_CKN: MCM8M_MOD1.29 U12.3(A0-)
CSI_P1_CKN_A: P8.18(MCN) U12.37(B0-)
CSI_P1_CKN_B: P46.24(MIPI_CLK_N) U12.33(C0-)
CSI_P1_CKP: MCM8M_MOD1.28 U12.2(A0+)
CSI_P1_CKP_A: P8.16(MCP) U12.38(B0+)
CSI_P1_CKP_B: P46.25(MIPI_CLK_P) U12.34(C0+)
CSI_P1_DN0: MCM8M_MOD1.33 U12.7(A1-)
CSI_P1_DN0_A: P8.22(MDN0) U12.35(B1-)
CSI_P1_DN0_B: P46.19(MIPI_D0_N) U12.31(C1-)
CSI_P1_DN1: MCM8M_MOD1.31 U12.12(A2-)
CSI_P1_DN1_A: P8.14(MDN1) U12.28(B2-)
CSI_P1_DN1_B: P46.15(MIPI_D1_N) U12.24(C2-)
CSI_P1_DN2: MCM8M_MOD1.27 P46.10(MIPI_D2_N)
CSI_P1_DN3: MCM8M_MOD1.25 P46.27(MIPI_D3_N)
CSI_P1_DP0: MCM8M_MOD1.32 U12.6(A1+)
CSI_P1_DP0_A: P8.20(MDP0) U12.36(B1+)
CSI_P1_DP0_B: P46.20(MIPI_D0_P) U12.32(C1+)
CSI_P1_DP1: MCM8M_MOD1.30 U12.11(A2+)
CSI_P1_DP1_A: P8.12(MDP1) U12.29(B2+)
CSI_P1_DP1_B: P46.16(MIPI_D1_P) U12.25(C2+)
CSI_P1_DP2: MCM8M_MOD1.26 P46.11(MIPI_D2_P)
CSI_P1_DP3: MCM8M_MOD1.24 P46.28(MIPI_D3_P)
CSI_PWR_DWN: P8.8(PWDN) Q1.3(D) R59.1 R60.2 R178.1
CSI_PWR_DWN_B: R179.1 U9.C1(B1)
CSI_RST: P8.6(RESET) R57.2 R174.1
CSTRB: P8.1(STROBE) R53.2 R55.2
DBG_UART_RXD: MCM8M_MOD1.64(29) ; also on sheet 11
DBG_UART_TXD: MCM8M_MOD1.63(28) ; also on sheet 11
DEBUGSEL: R158.1 ; also on sheet 11
DISP_RESET: R177.1 ; also on sheet 8
DS2_CON_DN: J3.2(D-) L10.2
DS2_CON_DP: J3.3(D+) L10.1
DSI_CKN: MCM8M_MOD1.39(4) ; also on sheet 8
DSI_CKP: MCM8M_MOD1.38(3) ; also on sheet 8
DSI_DN0: MCM8M_MOD1.43(8) ; also on sheet 8
DSI_DN1: MCM8M_MOD1.41(6) ; also on sheet 8
DSI_DN2: MCM8M_MOD1.37(2) ; also on sheet 8
DSI_DN3: MCM8M_MOD1.35 ; also on sheet 8
DSI_DP0: MCM8M_MOD1.42(7) ; also on sheet 8
DSI_DP1: MCM8M_MOD1.40(5) ; also on sheet 8
DSI_DP2: MCM8M_MOD1.36(1) ; also on sheet 8
DSI_DP3: MCM8M_MOD1.34 ; also on sheet 8
ECSPI1_MISO: MCM8M_MOD1.47(12) R307.2
ECSPI1_MOSI: MCM8M_MOD1.45(10) R306.2
ECSPI1_SCLK: MCM8M_MOD1.48(13) R308.2
ECSPI1_SS0: MCM8M_MOD1.46(11) R309.2
ENET_MDC: MCM8M_MOD1.115(10) U7.1(MDC)
ENET_MDIO: MCM8M_MOD1.116(11) R240.1 U7.48(MDIO)
ENET_nRST: R214.1 RN1.8(RA2) U7.2(~{RST})
ENET_RD0: MCM8M_MOD1.109(4) R255.1 U7.31(RXD0)
ENET_RD1: MCM8M_MOD1.110(5) R256.1 U7.30(RXD1)
ENET_RD2: MCM8M_MOD1.113(8) R252.1 U7.28(RXD2)
ENET_RD3: MCM8M_MOD1.114(9) R243.1 U7.27(RXD3)
ENET_RX_CTL: MCM8M_MOD1.111(6) R253.1 U7.32(RX_DV)
ENET_RXC: MCM8M_MOD1.112(7) R182.1 R244.1
ENET_TD0: MCM8M_MOD1.106(1) U7.36(TXD0)
ENET_TD1: MCM8M_MOD1.108(3) U7.37(TXD1)
ENET_TD2: MCM8M_MOD1.104(34) U7.38(TXD2)
ENET_TD3: MCM8M_MOD1.107(2) U7.39(TXD3)
ENET_TX_CTL: MCM8M_MOD1.105(35) U7.34(TX_EN)
ENET_TXC: MCM8M_MOD1.103(33) U7.35(GTX_CLK)
ENET_VIO: C27.2 C55.1 MCM8M_MOD1.117(12) R186.1 R240.2
ETH0_SHIELD: C69.1 FB1.1 P6.S1(SHIELD) P6.S2(SHIELD)
ETH1_CT1: C60.1 C61.1 P6.P5(CT) R40.1
ETH1_CT2: C66.1 P6.P6(CT)
ETH1_GREEN_LED_CAT: P6.P11(LED1_C) R46.1
ETH1_LED_ACT/PHY1ADDRESS2: P6.P12(LED1_A) R257.1 U7.23(LED_ACT)
ETH1_LINK-LED_10_100: D1.1(ANODE1) U7.26(LED_10_100)
ETH1_LINK-LED_1000/INTSELECT: D1.2(ANODE2) R254.1 U7.24(LED_1000)
ETH1_MDI0N: P6.P2(MDI0-) U7.12(TRXN0)
ETH1_MDI0P: P6.P1(MDI0+) U7.11(TRXP0)
ETH1_MDI1N: P6.P4(MDI1-) U7.15(TRXN1)
ETH1_MDI1P: P6.P3(MDI1+) U7.14(TRXP1)
ETH1_MDI2N: P6.P8(MDI2-) U7.18(TRXN2)
ETH1_MDI2P: P6.P7(MDI2+) U7.17(TRXP2)
ETH1_MDI3N: P6.P10(MDI3-) U7.21(TRXN3)
ETH1_MDI3P: P6.P9(MDI3+) U7.20(TRXP3)
ETH1_YELLOW_LED_AN: D1.3(CATHODE) P6.P14(LED2_A)
ETH1_YELLOW_LED_CAT: P6.P13(LED2_C) R47.1
EXPANDER_A0: R166.1 RN17.5(RD2) U35.18(A0)
EXPANDER_A1: R167.1 RN17.6(RC2) U35.23(A1)
EXPANDER_A2: R159.1 RN17.7(RB2) U35.24(A2)
GBEPHY1_CLK_XIN: C232.2 U7.7(XTLI) X4.1
GBEPHY1_CLK_XOUT: C233.2 U7.6(XTLO) X4.3
GPIO1_I13: MCM8M_MOD1.77(7) ; also on sheet 8
GPIO1_IO8: MCM8M_MOD1.85(15) ; also on sheet 14
GPIO_PHY1_INT: MCM8M_MOD1.78(8) R185.2
GPIO_PHY1_RST: MCM8M_MOD1.79(9) R214.2
GPIO_PHY1_WOL: MCM8M_MOD1.83(13) R241.2
GPIO_USB_ID: MCM8M_MOD1.86(16) R171.2
HUB_OE: R239.2 U34.8(\\~{O}E)
I2C1_SCL: MCM8M_MOD1.53(18) R160.2 R205.2 U35.19(SCL) ; also on sheet 11
I2C1_SDA: MCM8M_MOD1.54(19) R188.2 R204.2 U35.20(SDA) ; also on sheet 11
I2C3_SCL: MCM8M_MOD1.58(23) ; also on sheet 14
I2C3_SDA: MCM8M_MOD1.57(22) ; also on sheet 14
I2C4_SCL: R202.1 R205.1 U10.28(SCLK) U14.1(B2) ; also on sheet 8 9
I2C4_SCL_CM: MCM8M_MOD1.56(21) R190.2 R202.2
I2C4_SDA: R203.1 R204.1 U10.27(SDIN) U14.8(B1) ; also on sheet 8 9
I2C4_SDA_CM: MCM8M_MOD1.55(20) R189.2 R203.2
INT_EXP: R234.1 R235.2 U35.22(\\~{IN}T)
INT_I2C_EXP: MCM8M_MOD1.88(18) R234.2
J_MOD_8: P7.7 R155.2
JTAG_HDR_10: P7.9 R51.2 R52.2
JTAG_MOD: MCM8M_MOD1.134(29) R155.1
JTAG_nTRST: MCM8M_MOD1.135(30) R52.1
JTAG_RST: D10.CATHODE P7.10 R162.1
JTAG_TCK: MCM8M_MOD1.133(28) P7.4
JTAG_TDI: MCM8M_MOD1.131(26) P7.8
JTAG_TDO: MCM8M_MOD1.132(27) P7.6
JTAG_TMS: MCM8M_MOD1.130(25) P7.2
JUMP: E5.2 R79.2
LCDINT_GPIO1_IO1: MCM8M_MOD1.87(17) ; also on sheet 8 14
LHPOUT: C41.1 P5.4(L) R19.1
LHPOUT_T: C41.2 U10.13(LHPOUT)
LIN_T: C39.2 C42.1 R22.1 R25.2
LLINEIN: P4.4(L) R22.2
LLINEIN_T: C39.1 U10.24(LLINEIN)
MCLK_B: P46.13(RSVD1) R209.2
MCLK_VCC: C81.1 OSC1.4(VCC) R64.2 R67.1
MCLK_VCC_B: C87.1 OSC2.4(VCC) R73.2 R74.1 R78.1
MIC_IN: C28.1 C29.2 P3.4(L) R16.2 R18.1
MICBIAS: R16.1 U10.21(MICBIAS)
MICIN: R17.2 U10.22(MICIN)
MIPICAM_DVDD1V5: C78.1 P8.10(DVDD1.5V) R61.1
mPCIe_PERST: R156.1 ; also on sheet 9
MUX_PCI_USB_DN: U34.6(HSD2-) ; also on sheet 9
MUX_PCI_USB_DP: U34.2(HSD2+) ; also on sheet 9
MUX_USB_CON_DN: L10.3 U34.7(HSD1-)
MUX_USB_CON_DP: L10.4 U34.1(HSD1+)
OSC2_EN: OSC2.1(EN) R77.2 R78.2
OSC2_OUT: OSC2.3(OUT) U37.1(A) U37.2(B)
OSC25MHZ: OSC1.3(OUT) R65.2
OSCEN: OSC1.1(EN) R68.1 R69.2 R70.1
OTG_DN: L7.2 P17.2(D-)
OTG_DP: L7.1 P17.3(D+)
PB_ALT_BOOT: R270.2 SW9.2 SW9.4 ; also on sheet 13
PB_RESET: R268.2 SW8.2 SW8.4 ; also on sheet 13
PCIE1_REF_CLKN: MCM8M_MOD1.16 ; also on sheet 9
PCIE1_REF_CLKP: MCM8M_MOD1.17 ; also on sheet 9
PCIE1_RXN_N: MCM8M_MOD1.19 ; also on sheet 9
PCIE1_RXN_P: MCM8M_MOD1.18 ; also on sheet 9
PCIE1_TXN_N: MCM8M_MOD1.20 ; also on sheet 9
PCIE1_TXN_P: MCM8M_MOD1.21 ; also on sheet 9
PHY1_INT: R185.1 RN1.6(RC2) U7.5(INT)
PHY1_WOL: R241.1 RN1.7(RB2) U7.40(WOL_INT)
PHY_RXC: R182.2 U7.33(RX_CLK)
PMIC_ON_REQ: MCM8M_MOD1.44(9) ; also on sheet 10 14
PMIC_STBY_REQ: MCM8M_MOD1.23 ; also on sheet 14
POR_B: D10.ANODE MCM8M_MOD1.14 R162.2 R268.1 ; also on sheet 8 9 13 14
PWDN_CAM_DLY: C79.2 Q1.1(G) R62.2
PWR_I2C4: R189.1 R190.1 R201.1
PWRBTN: MCM8M_MOD1.3 R273.1
QSPIA_DATA0: MCM8M_MOD1.9 ; also on sheet 11
QSPIA_DATA1: MCM8M_MOD1.5 ; also on sheet 11
QSPIA_DATA2: MCM8M_MOD1.6 ; also on sheet 11
QSPIA_DATA3: MCM8M_MOD1.8 ; also on sheet 11
QSPIA_nSS0: MCM8M_MOD1.7 ; also on sheet 11
QSPIA_SCLK: MCM8M_MOD1.10 ; also on sheet 11
Res_ ATP: MCM8M_MOD1.80(10) ; also on sheet 13
RGMII_AVDDL_1P1: C202.1 C229.1 C230.1 C234.1 L9.2 U7.8(AVDDL1) U7.13(AVDDL3) U7.19(AVDDL4) U7.44(AVDDL2)
RGMII_DVDDL_1V1: C227.1 C228.1 C231.1 L9.1 L11.2 R194.2 U7.47(DVDDL)
RGMII_LX: L11.1 U7.3(LX)
RGMII_VDDH_2V5: C191.2 C201.1 R184.1 R186.2 U7.10(VDDH_REG)
RHPOUT: C40.1 P5.3(R) R27.1
RHPOUT_T: C40.2 U10.14(RHPOUT)
RIN_T: C38.2 C43.1 R21.1 R26.2
RLINEIN: P4.3(R) R21.2
RLINEIN_T: C38.1 U10.23(RLINEIN)
SAI1_MCLK: MCM8M_MOD1.95(25) ; also on sheet 14
SAI1_RXC: MCM8M_MOD1.92(22) ; also on sheet 14
SAI1_RXD0: MCM8M_MOD1.91(21) R314.2
SAI1_RXFS: MCM8M_MOD1.93(23) ; also on sheet 14
SAI1_TXC: MCM8M_MOD1.90(20) ; also on sheet 14
SAI1_TXD0: MCM8M_MOD1.89(19) R312.2
SAI1_TXFS: MCM8M_MOD1.94(24) R311.2
SAI2_MCLK: MCM8M_MOD1.99(29) R28.2
SAI2_RXC: MCM8M_MOD1.97(27) ; also on sheet 14
SAI2_RXD: MCM8M_MOD1.102(32) U10.10(ADCDAT)
SAI2_RXFS: MCM8M_MOD1.96(26) R24.2
SAI2_TXC: MCM8M_MOD1.100(30) R20.1
SAI2_TXD: MCM8M_MOD1.98(28) U10.8(DACDAT)
SAI2_TXFS: MCM8M_MOD1.101(31) R23.2 U10.9(DACLRC)
SD1_CLK: MCM8M_MOD1.118(13) ; also on sheet 12
SD1_CMD: MCM8M_MOD1.126(21) ; also on sheet 12
SD1_DATA0: MCM8M_MOD1.122(17) ; also on sheet 12
SD1_DATA1: MCM8M_MOD1.123(18) ; also on sheet 12
SD1_DATA2: MCM8M_MOD1.129(24) ; also on sheet 12
SD1_DATA3: MCM8M_MOD1.119(14) ; also on sheet 12
SD1_DATA4: MCM8M_MOD1.128(23) ; also on sheet 12
SD1_DATA5: MCM8M_MOD1.127(22) ; also on sheet 12
SD1_DATA6: MCM8M_MOD1.124(19) ; also on sheet 12
SD1_DATA7: MCM8M_MOD1.125(20) ; also on sheet 12
SD1_RESET: MCM8M_MOD1.121(16) ; also on sheet 12
SD1_STROBE: MCM8M_MOD1.120(15) ; also on sheet 14
SD2_CLK: MCM8M_MOD1.70(35) ; also on sheet 11
SD2_CMD: MCM8M_MOD1.69(34) ; also on sheet 11
SD2_DATA0: MCM8M_MOD1.72(2) ; also on sheet 11
SD2_DATA1: MCM8M_MOD1.73(3) ; also on sheet 11
SD2_DATA2: MCM8M_MOD1.68(33) ; also on sheet 11
SD2_DATA3: MCM8M_MOD1.67(32) ; also on sheet 11
SD2_nCD: MCM8M_MOD1.74(4) ; also on sheet 11
SD2_nRST: MCM8M_MOD1.75(5) ; also on sheet 14
SD2_WP: MCM8M_MOD1.71(1) ; also on sheet 14
SPDIF_EXT_CLK: MCM8M_MOD1.81(11) ; also on sheet 14
SPDIF_OUT1C: C49.1 R33.1
SPDIF_RX: MCM8M_MOD1.84(14) U11.2(12)
SPDIF_TX: C49.2 MCM8M_MOD1.82(12)
SW_BOOT: R266.2 SW9.1 SW9.3
SW_PWRBTN: R269.1 SW10.1 SW10.3
SW_RES: R267.1 SW8.1 SW8.3
SWPWRBTN: R273.2 SW10.2 SW10.4
SYS_I2C_SCL: MCM8M_MOD1.11 ; also on sheet 14
SYS_I2C_SDA: MCM8M_MOD1.12 ; also on sheet 14
TOUCH_RESET: R196.1 ; also on sheet 8
TP17: MCM8M_MOD1.22 TP17.1
TXS0104_OE: R72.2 U9.B3(OE)
U9_A1: R230.2 U9.A1
U9_A2: R231.2 U9.A2
U9_A3: R232.2 U9.A3
U9_A4: R258.2 U9.A4
U12_15: R84.2 U12.15(A3+)
U12_16: R81.2 U12.16(A3-)
U37_4: R209.1 U37.4(A+B)
U52_STBY: R313.2 U52.8(STBY)
UART1_RXD/ECSPI3_SCLK: MCM8M_MOD1.60(25) ; also on sheet 14
UART1_TXD/ECSPI3_MOSI: MCM8M_MOD1.59(24) ; also on sheet 14
UART2_RXD/ECSPI3_MISO: MCM8M_MOD1.61(26) ; also on sheet 11 14
UART2_TXD/ECSPI3_SS0: MCM8M_MOD1.62(27) ; also on sheet 11 14
UART4_CTS/ECSPI2_MISO: MCM8M_MOD1.50(15) ; also on sheet 12 14
UART4_RTS/ECSPI2_SS0: MCM8M_MOD1.49(14) ; also on sheet 12 14
UART4_RXD: MCM8M_MOD1.66(31) ; also on sheet 14
UART4_RXD/ECSPI2_SCLK: MCM8M_MOD1.52(17) ; also on sheet 12 14
UART4_SEL: R337.1 ; also on sheet 12
UART4_TXD: MCM8M_MOD1.65(30) ; also on sheet 14
UART4_TXD/ECSPI2_MOSI: MCM8M_MOD1.51(16) ; also on sheet 12 14
USB1_DN: L7.3 MCM8M_MOD1.140(35)
USB1_DP: L7.4 MCM8M_MOD1.139(34)
USB1_EN: R63.1 R238.1 U33.1(EN_A)
USB1_ID: MCM8M_MOD1.1 R153.2
USB1_ID_CONN: R151.1 R153.1 R171.1 R237.2 U11.9(I)
USB1_ID_CONN_R: P17.4(ID) R237.1
USB1_VBUS_DET: MCM8M_MOD1.2 R152.1
USB1_VBUS_EN: R238.2 U11.8(12)
USB2_DN: MCM8M_MOD1.137(32) U34.5(D-)
USB2_DP: MCM8M_MOD1.136(31) U34.3(D+)
USB2_VBUS_DET: MCM8M_MOD1.138(33) R154.1
USB2_VBUS_EN: R236.2 U11.6(12)
USB2_VBUS_EN_R: R43.1 R236.1 U33.4(EN_B)
USB_MUX_SEL: E14.2 R2.2 R172.1 U11.5(I) U34.10(SEL)
USBMUX_SEL: R2.1 R157.1
V_SOM: C2.1 C3.1 C5.1 C6.1 C7.1 C8.1 C9.1 C10.1 C11.1 C12.1 C13.1 C63.1 C65.1 C70.1 C83.1 C236.2 C237.2 C238.2 C239.2 MCM8M_MOD1.4 MCM8M_MOD1.15 MCM8M_MOD1.141(V_SOM) ; also on sheet 8 10 14
VIO_CAMERA: C73.1 C84.1 C85.1 C88.1 R54.2 R56.2 R72.1 R233.2 R242.2 U9.B2(VCCA) U14.3(VCCA) U37.5(VCC)
VSB_1V5: R61.2 ; also on sheet 9 10
VSB_1V8: C80.2 C89.1 P8.11(DVDD1.8V/2.8V) P46.3(VCC_1P8) R58.1 R59.2 R67.2 R70.2 R74.2 R242.1 ; also on sheet 8 10 12 14
VSB_2V8: C74.2 C75.1 C76.1 P8.4(AVDD) P8.23(AF-VCC2.8V) R53.1 R62.1 R68.2 ; also on sheet 10

Not connected (* = marked no-connect by the designer): FID1 1*; FID2 1*; FID3 1*; FID4 1*; FID5 1*; FID6 1*; P3 2(AUX)* 3(R)* CN* CO*; P4 CN* CO*; P5 CN* CO*; P8 7(NC)* 9(NC)* 17(NC)* 19(NC)* 21(NC)*; RN1 4(RD1)* 5(RD2)*; RN17 1(RA1)* 8(RA2)*; U7 22(PPS/GPIO)* 25(CLK_25M)* 42(SON)* 43(SOP)* 45(SIN)* 46(SIP)*; U10 6(CLKOUT)* 16(LOUT)* 17(ROUT)*; U12 22(C3-)* 23(C3+)* 26(B3-)* 27(B3+)*; U33 2(FLG_A)* 3(FLG_B)*; U47 3(CLKO/SOF)*

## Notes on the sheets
sheet 1
- DNP
- ALT5
  gpio4_IO[10]
  gpio4_IO[12]
  gpio4_IO[2]
- DNP
sheet 2
- SB-MCM-MX8M
- BOARD REVISION: 1.0
- PAGE
- DESCRIPTION
- 01
- Index
- 02
- Carrier-board interface
- 03
- Gigabit Ethernet
- 04
- USB
- 05
- Audio
- 06
- JTAG, CSI, GPIO expander
- 07
- MIPI LCD
- 08
- PCIe
- 09
- Power
- 10
- UART, RS232, SD, EEPROM, QSPI
- 11
- WIFI&Bluetooth, RS485
- 12
- ALT Boot
- CAN interfaces
- 13
- 14
- Mechanical,MISC connectors
sheet 3
- UP
- POWER/RESET/BOOT SWITCHES
- RIGHT
- LEFT
- V-SOM decoupling capacitors
- DOWN
sheet 4
- GbE PHY
- RefDes for
  RGMII IO
- REG OUT
- Near p29
- Near p10
- REG OUT
- CP
- AVDD33_ETH  to connector
  for CM of magnetic
- Ind2_5x2x1_2
- POWER CONSUMPTION:
  471.9mW (typ, not including LEDs).
  Assuming LEDs are 2mA per LED.
  ((480/3.3+3*2)=~150mA @ 3.3V
- Ethernet connector
- DNP
- Place near each
  AVDDL pin
- MODE[2]
- PHYADDRESS0
- 100 Ohm
- PHYADDRESS1
- MODE[1]
- MODE[3]
- 100 Ohm
- MODE[0]
- 100 Ohm
- REFDES
  Provision
- 100 Ohm
- 1.2V DOMAIN
- bypass on p5
- 2.5V or 3.3V
- PHYADDRESS2
- STRAPS
- MODE[3:0]
  0000 ==> AR8033 IS IN
  1000 BASE-T <-> RGMII mode
- MODE[3]
- MODE[2]
- MODE[1]
- MODE[0]
- LED ACTIVE HIGH
- PHYADDRESS0
- PHYADDRESS1
- PHYADDRESS2
- AR8033 PHYSICAL
  ADDRESS IS 00000
sheet 5
- USB2.0 OTG
- DNP
- Active high >2.4
- DNP
- USB OTG CONN.
- USB2.0 HOST
- 90 ohm
- DNP
sheet 6
- MIC IN
- Audio Codec
- POWER CONSUMPTION:
  DBVDD = 1.5mA @ 3.3V (typ)
  DCVDD = 3.2mA @ 1.5V (typ) ==> assuming same current @ 3.3V
  HPVDD = 1.7mA @ 3.3V (typ)
  AVDD = 13.1mA @ 3.3V (typ)
  1.5+3.2+1.7+13.1=19.5mA @ 3.3V (typ):
  Assuming worst case is 50mA @ 3.3V
- Place C30 and C31
  ACAP to U10 pins 5 and 4
- Place C32 and C33
  ACAP to U10 pins 3 and 4
- Place C36 and C37
  ACAP to U10 pins 18 and 19
- Place C95 and C170
  ACAP to U10 pins 12 and 15
- AUDIO IN
- I2C ADDRESS: 0b0011010 (0x1AH)
- DNP
- AUDIO OUT
- Keep analog signals clear from other signals at least 30mills
  Analog signals list will be provided in separate doc
- DNP
- DNP
- DNP
- DNP
- 20mil
- 20mil
- NOT CP
- Keep S1 close to U11
  S1 width at least 20 mil
- DNP
- SPDIF
sheet 7
- JTAG
- 30 pin Connector for e-CAM130_iMX8M
  (e-con System)
- NXP refdes layout
- TCK
- TMS
- GND
- VCC
- TDO
- GND
- DNP
- TDI
- DNP
- MIPI 4-lane
  camera module
- I2C to GPIO expander
- OE VCCA
  domain
- DNP
- DNP
- I2C address: 0x20
- DNP
- DNP
- DNP
- I2C connection provision
- DNP
- MUX: Vcm=0-2V; Vpp=1.6V
  CSI:Vcm=150-250mV;Vpp=270mV
- DNP
- Camera module: LI-OV5640-MIPI-AF
- DNP
- Default I2C address (SCCB slave ID): 0x78
- DNP
- DNP
- DNP
- DNP
- DNP
- up to 140mA
- DNP
- 2 Line
- LI-OV5640 camera module connector
- DNP
